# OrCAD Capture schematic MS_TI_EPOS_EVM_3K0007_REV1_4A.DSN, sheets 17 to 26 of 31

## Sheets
17 Pg17: UART #1 RS-232: size C
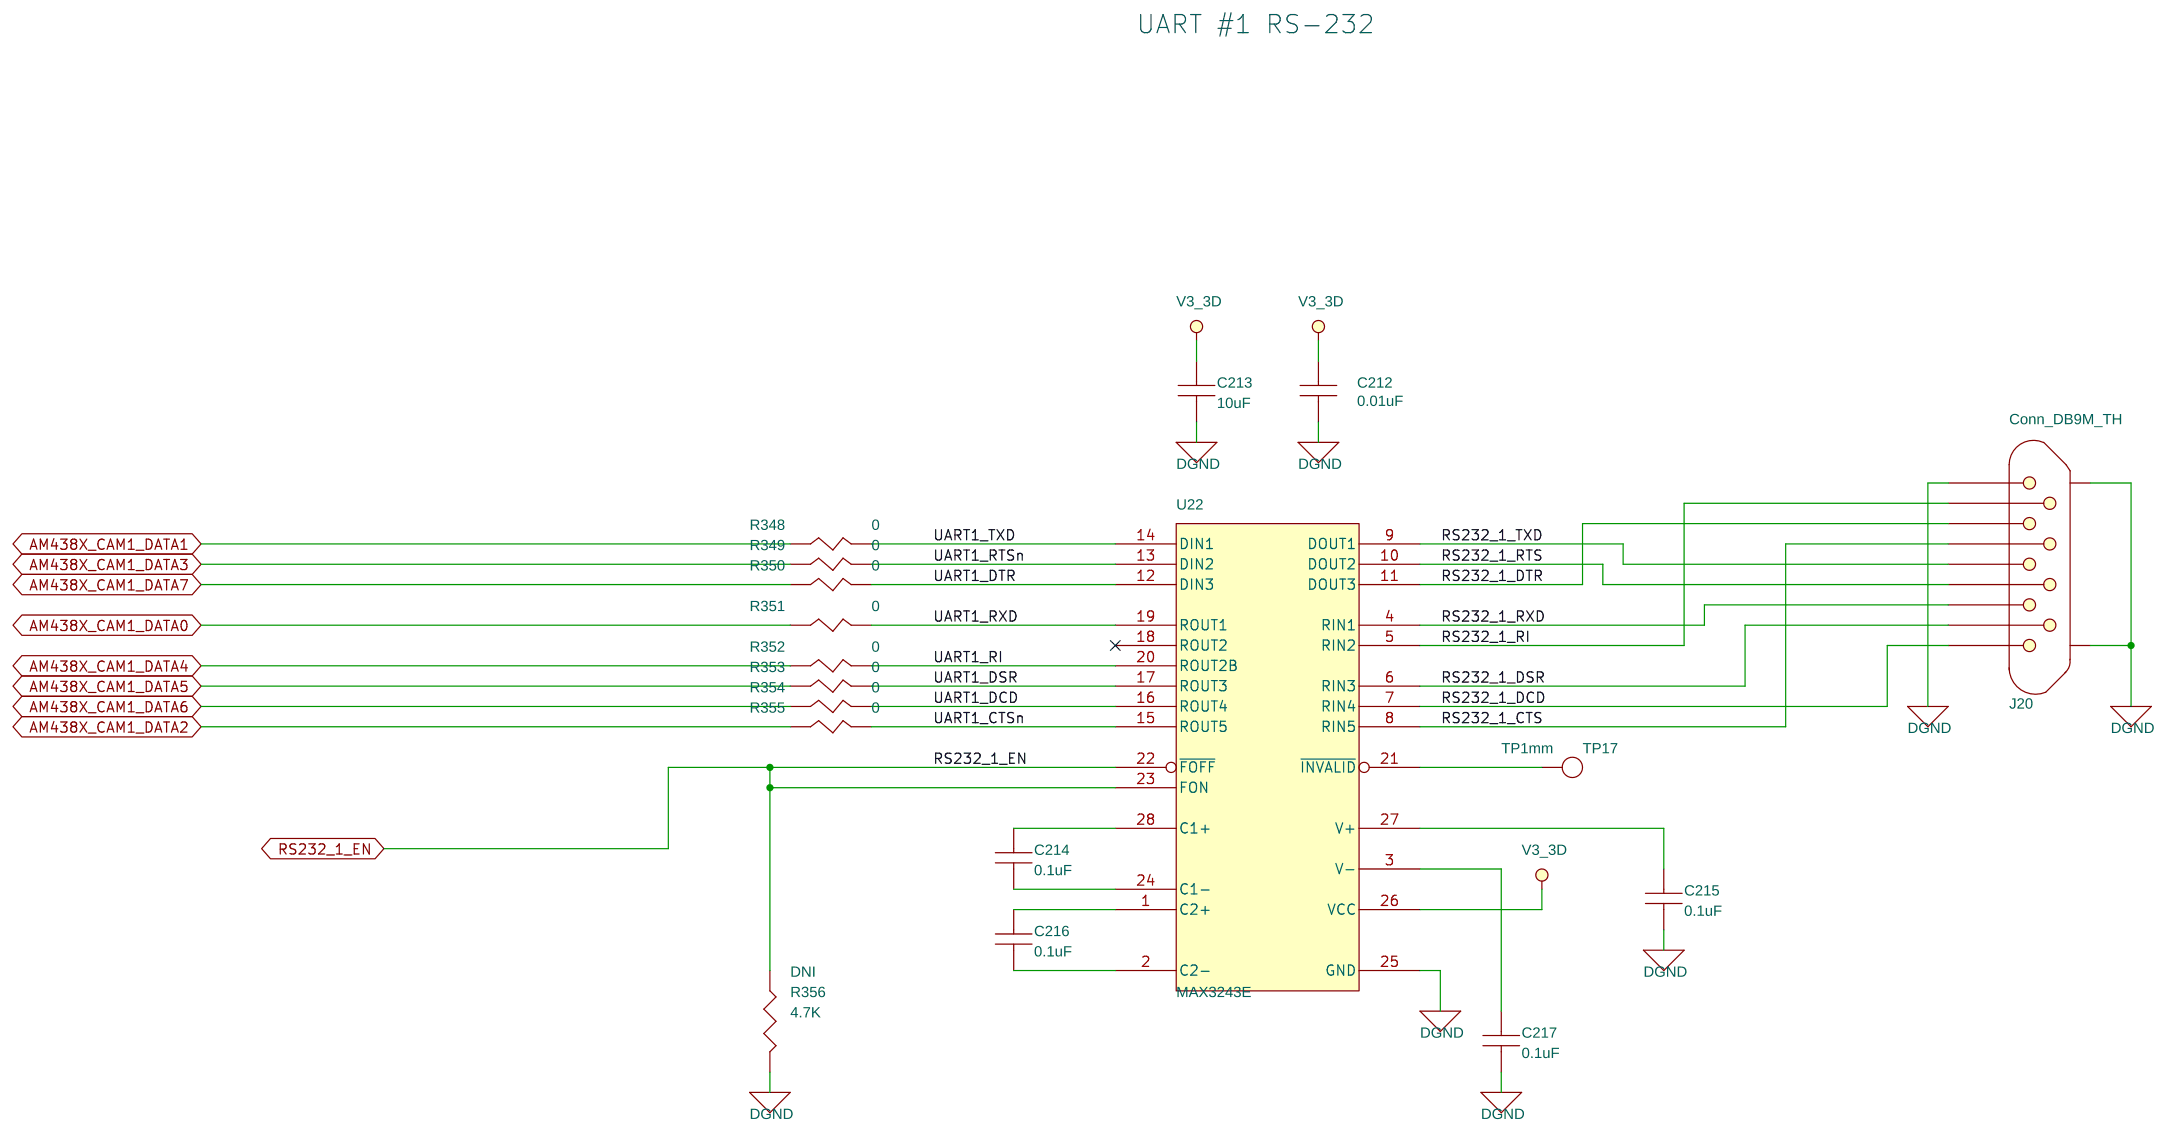
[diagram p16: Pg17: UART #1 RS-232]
18 Pg29: Power Monitor: size C
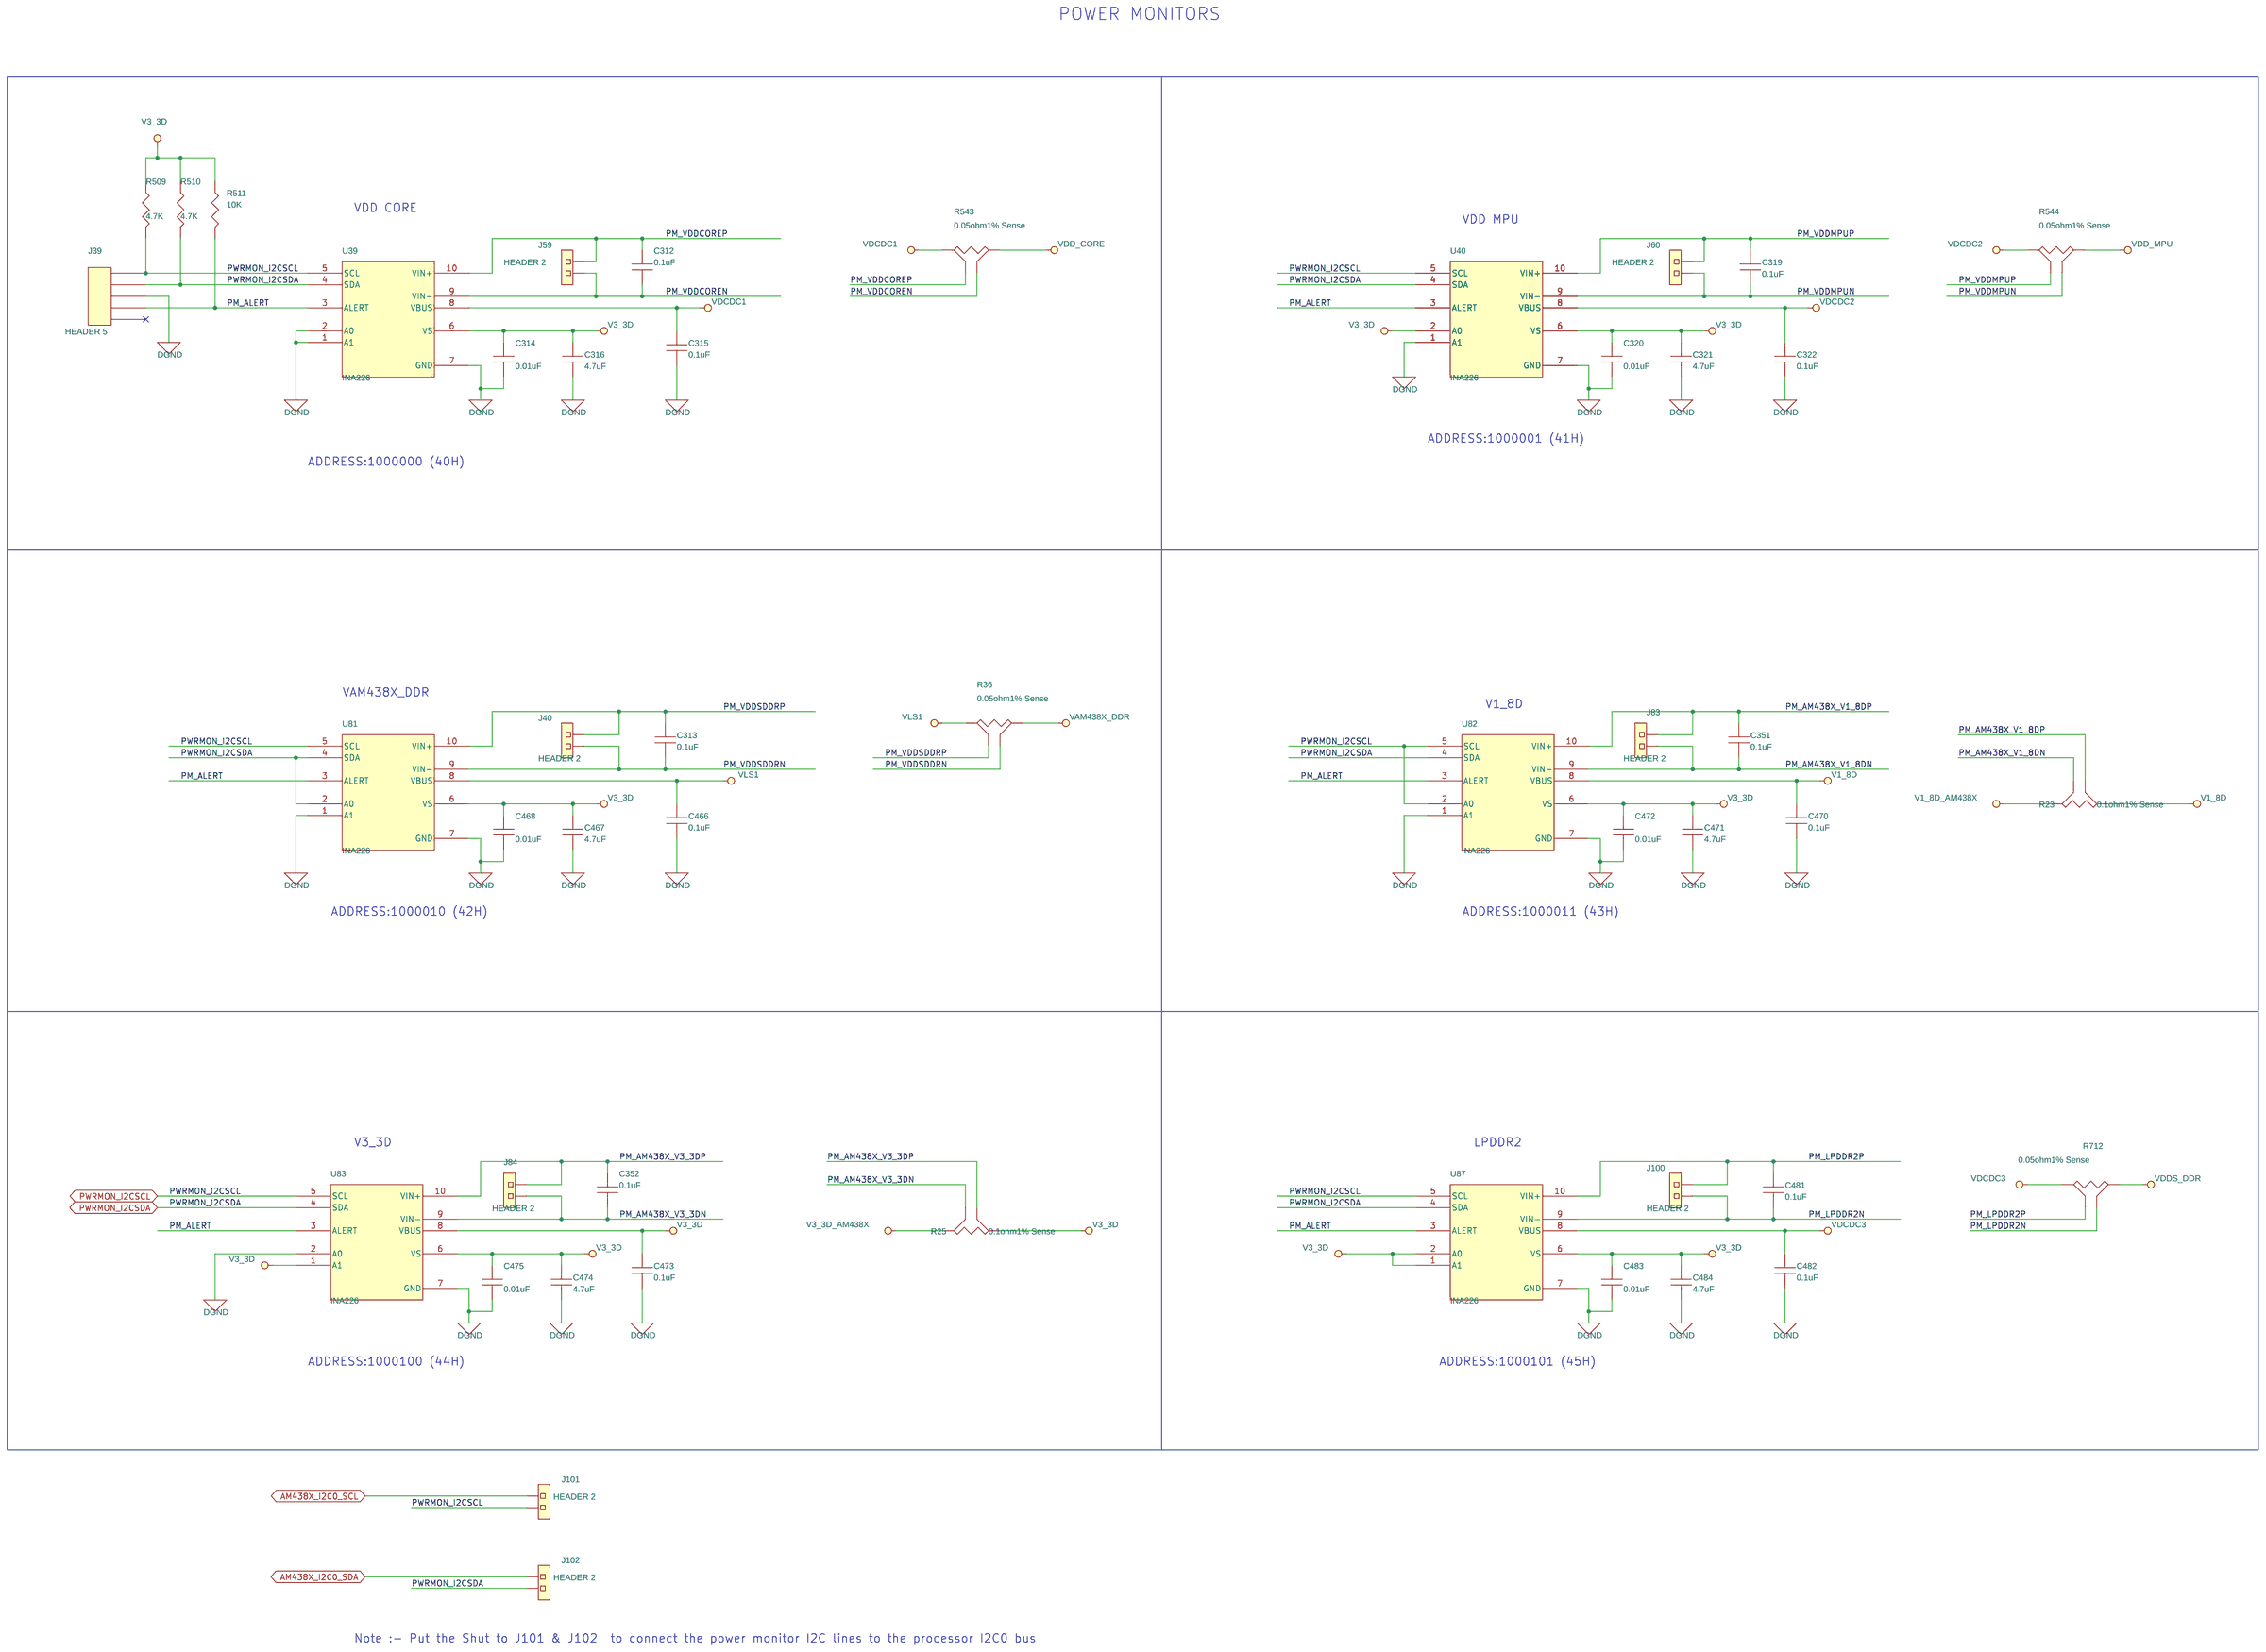
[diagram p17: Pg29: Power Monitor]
19 Pg18: Wireless COM8: size C
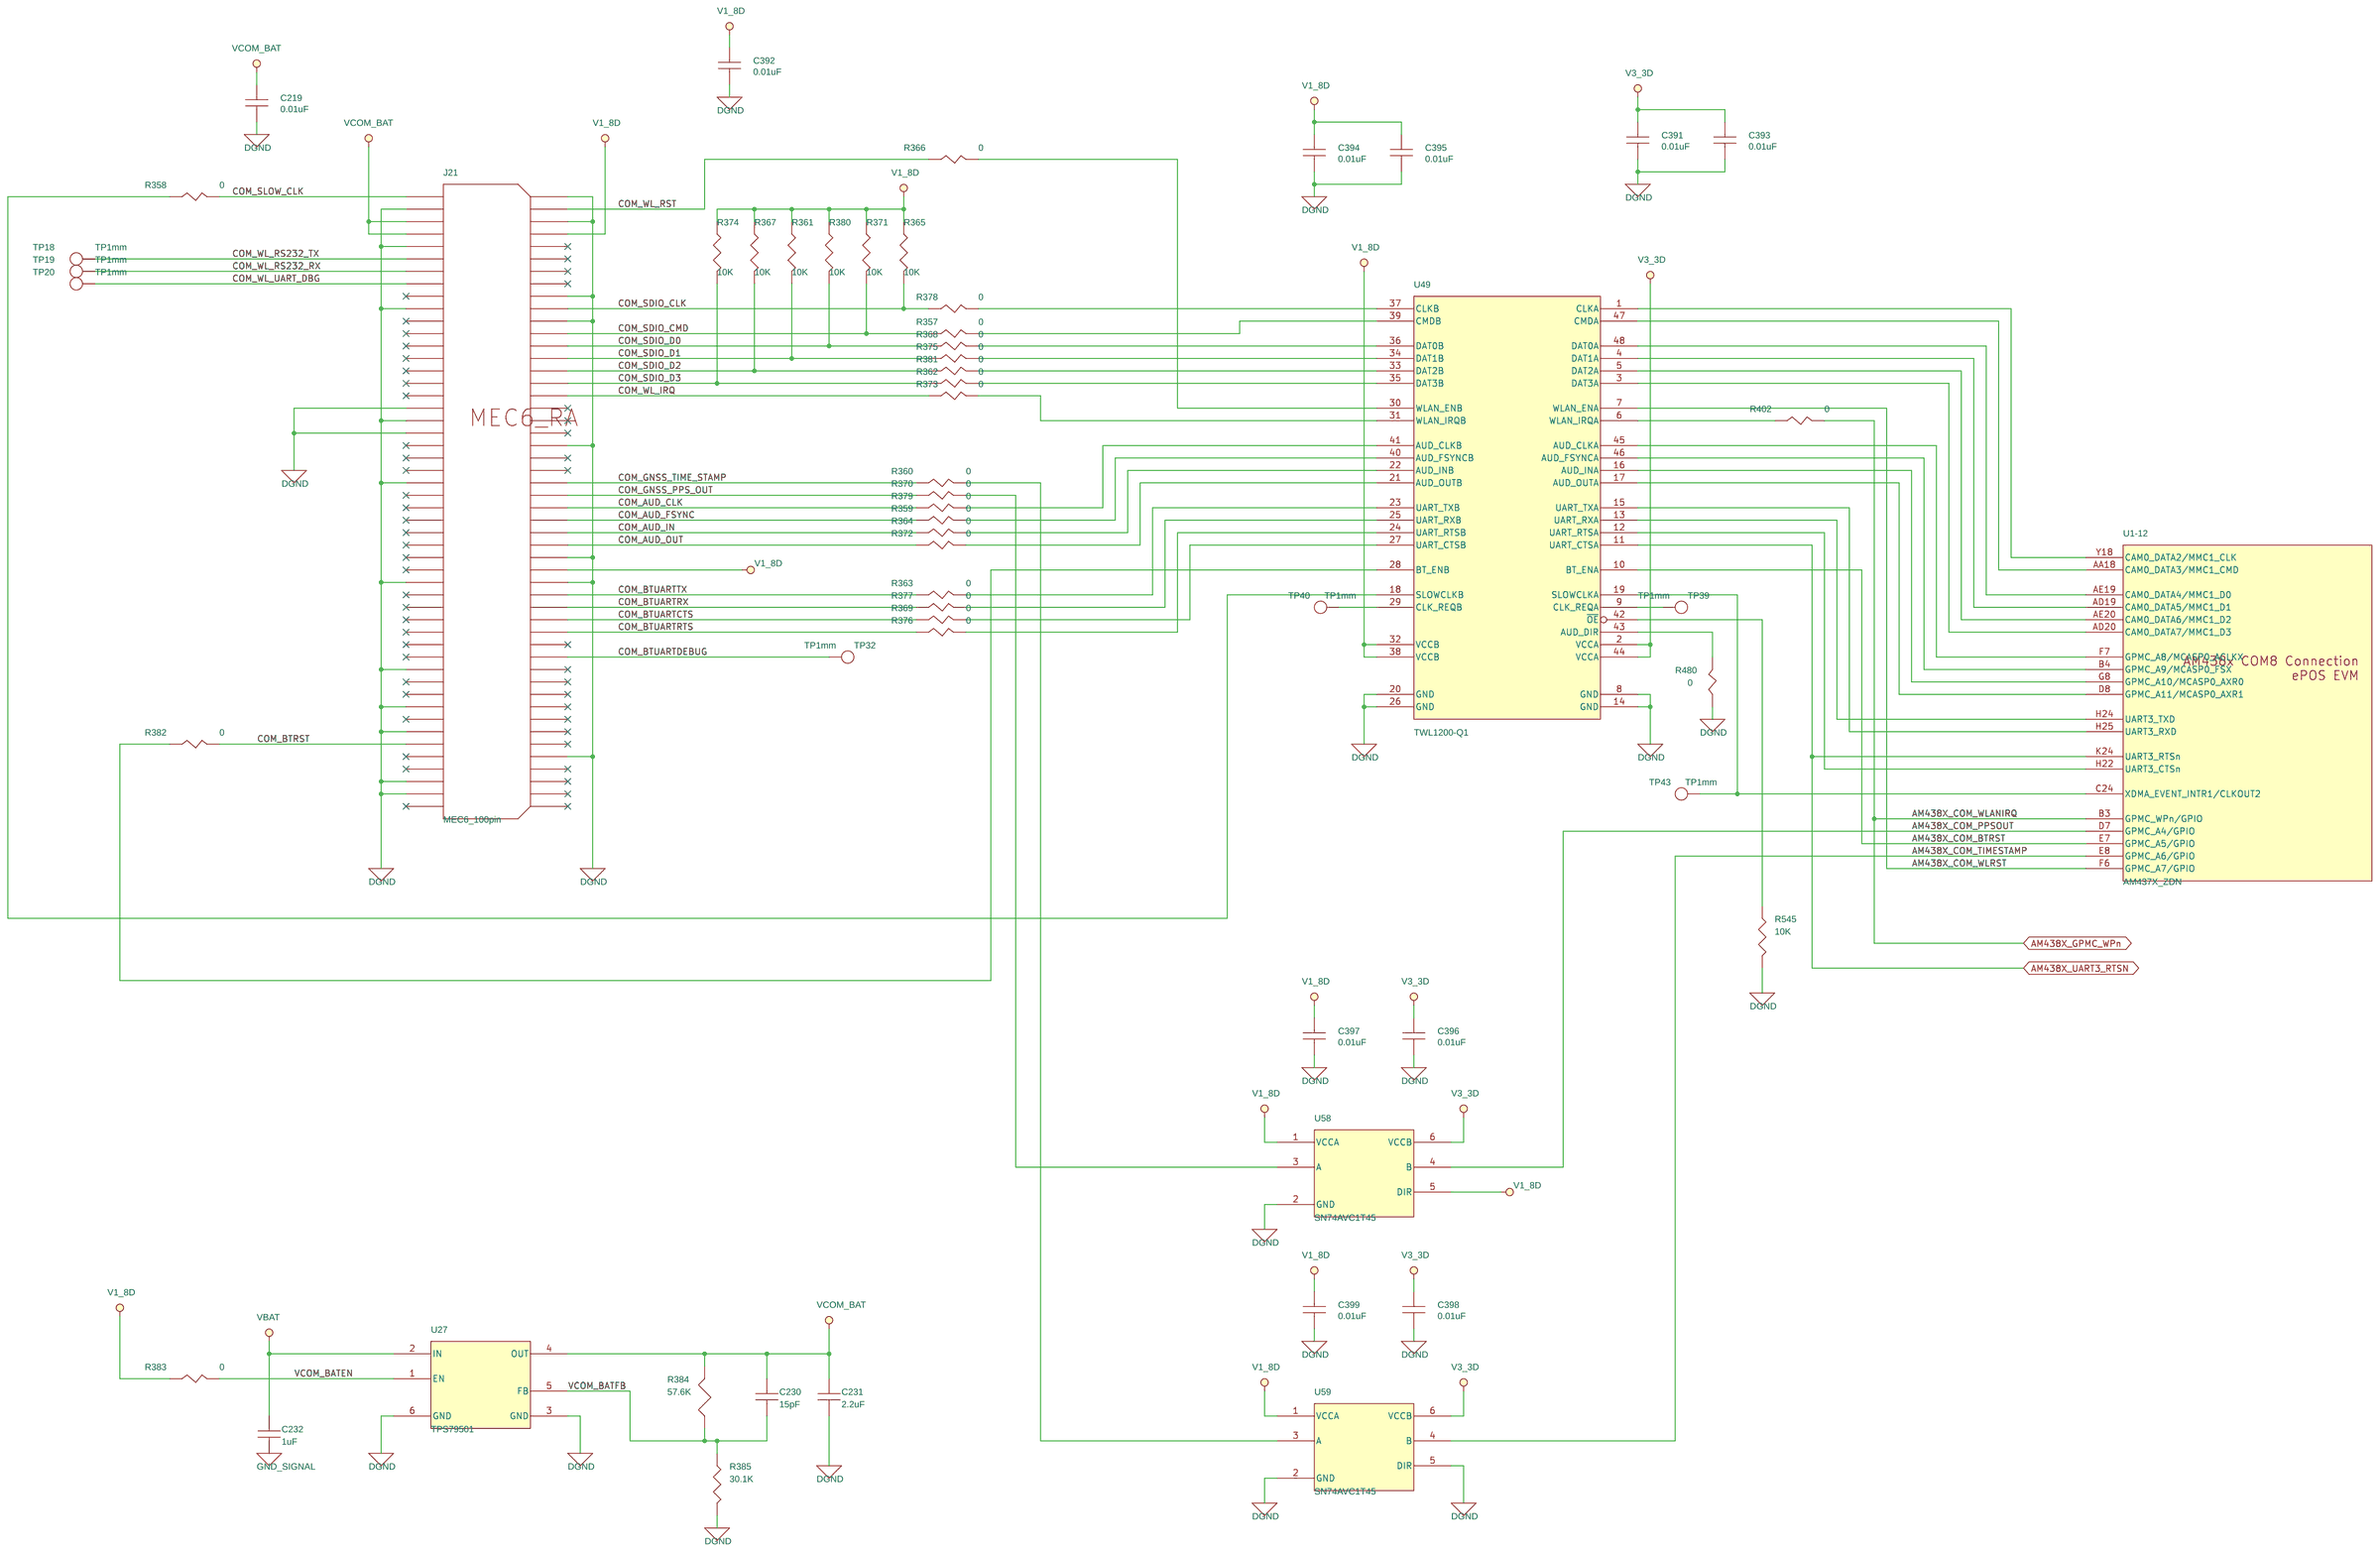
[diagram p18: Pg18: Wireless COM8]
20 Pg16: UART #0 RS-232: size C
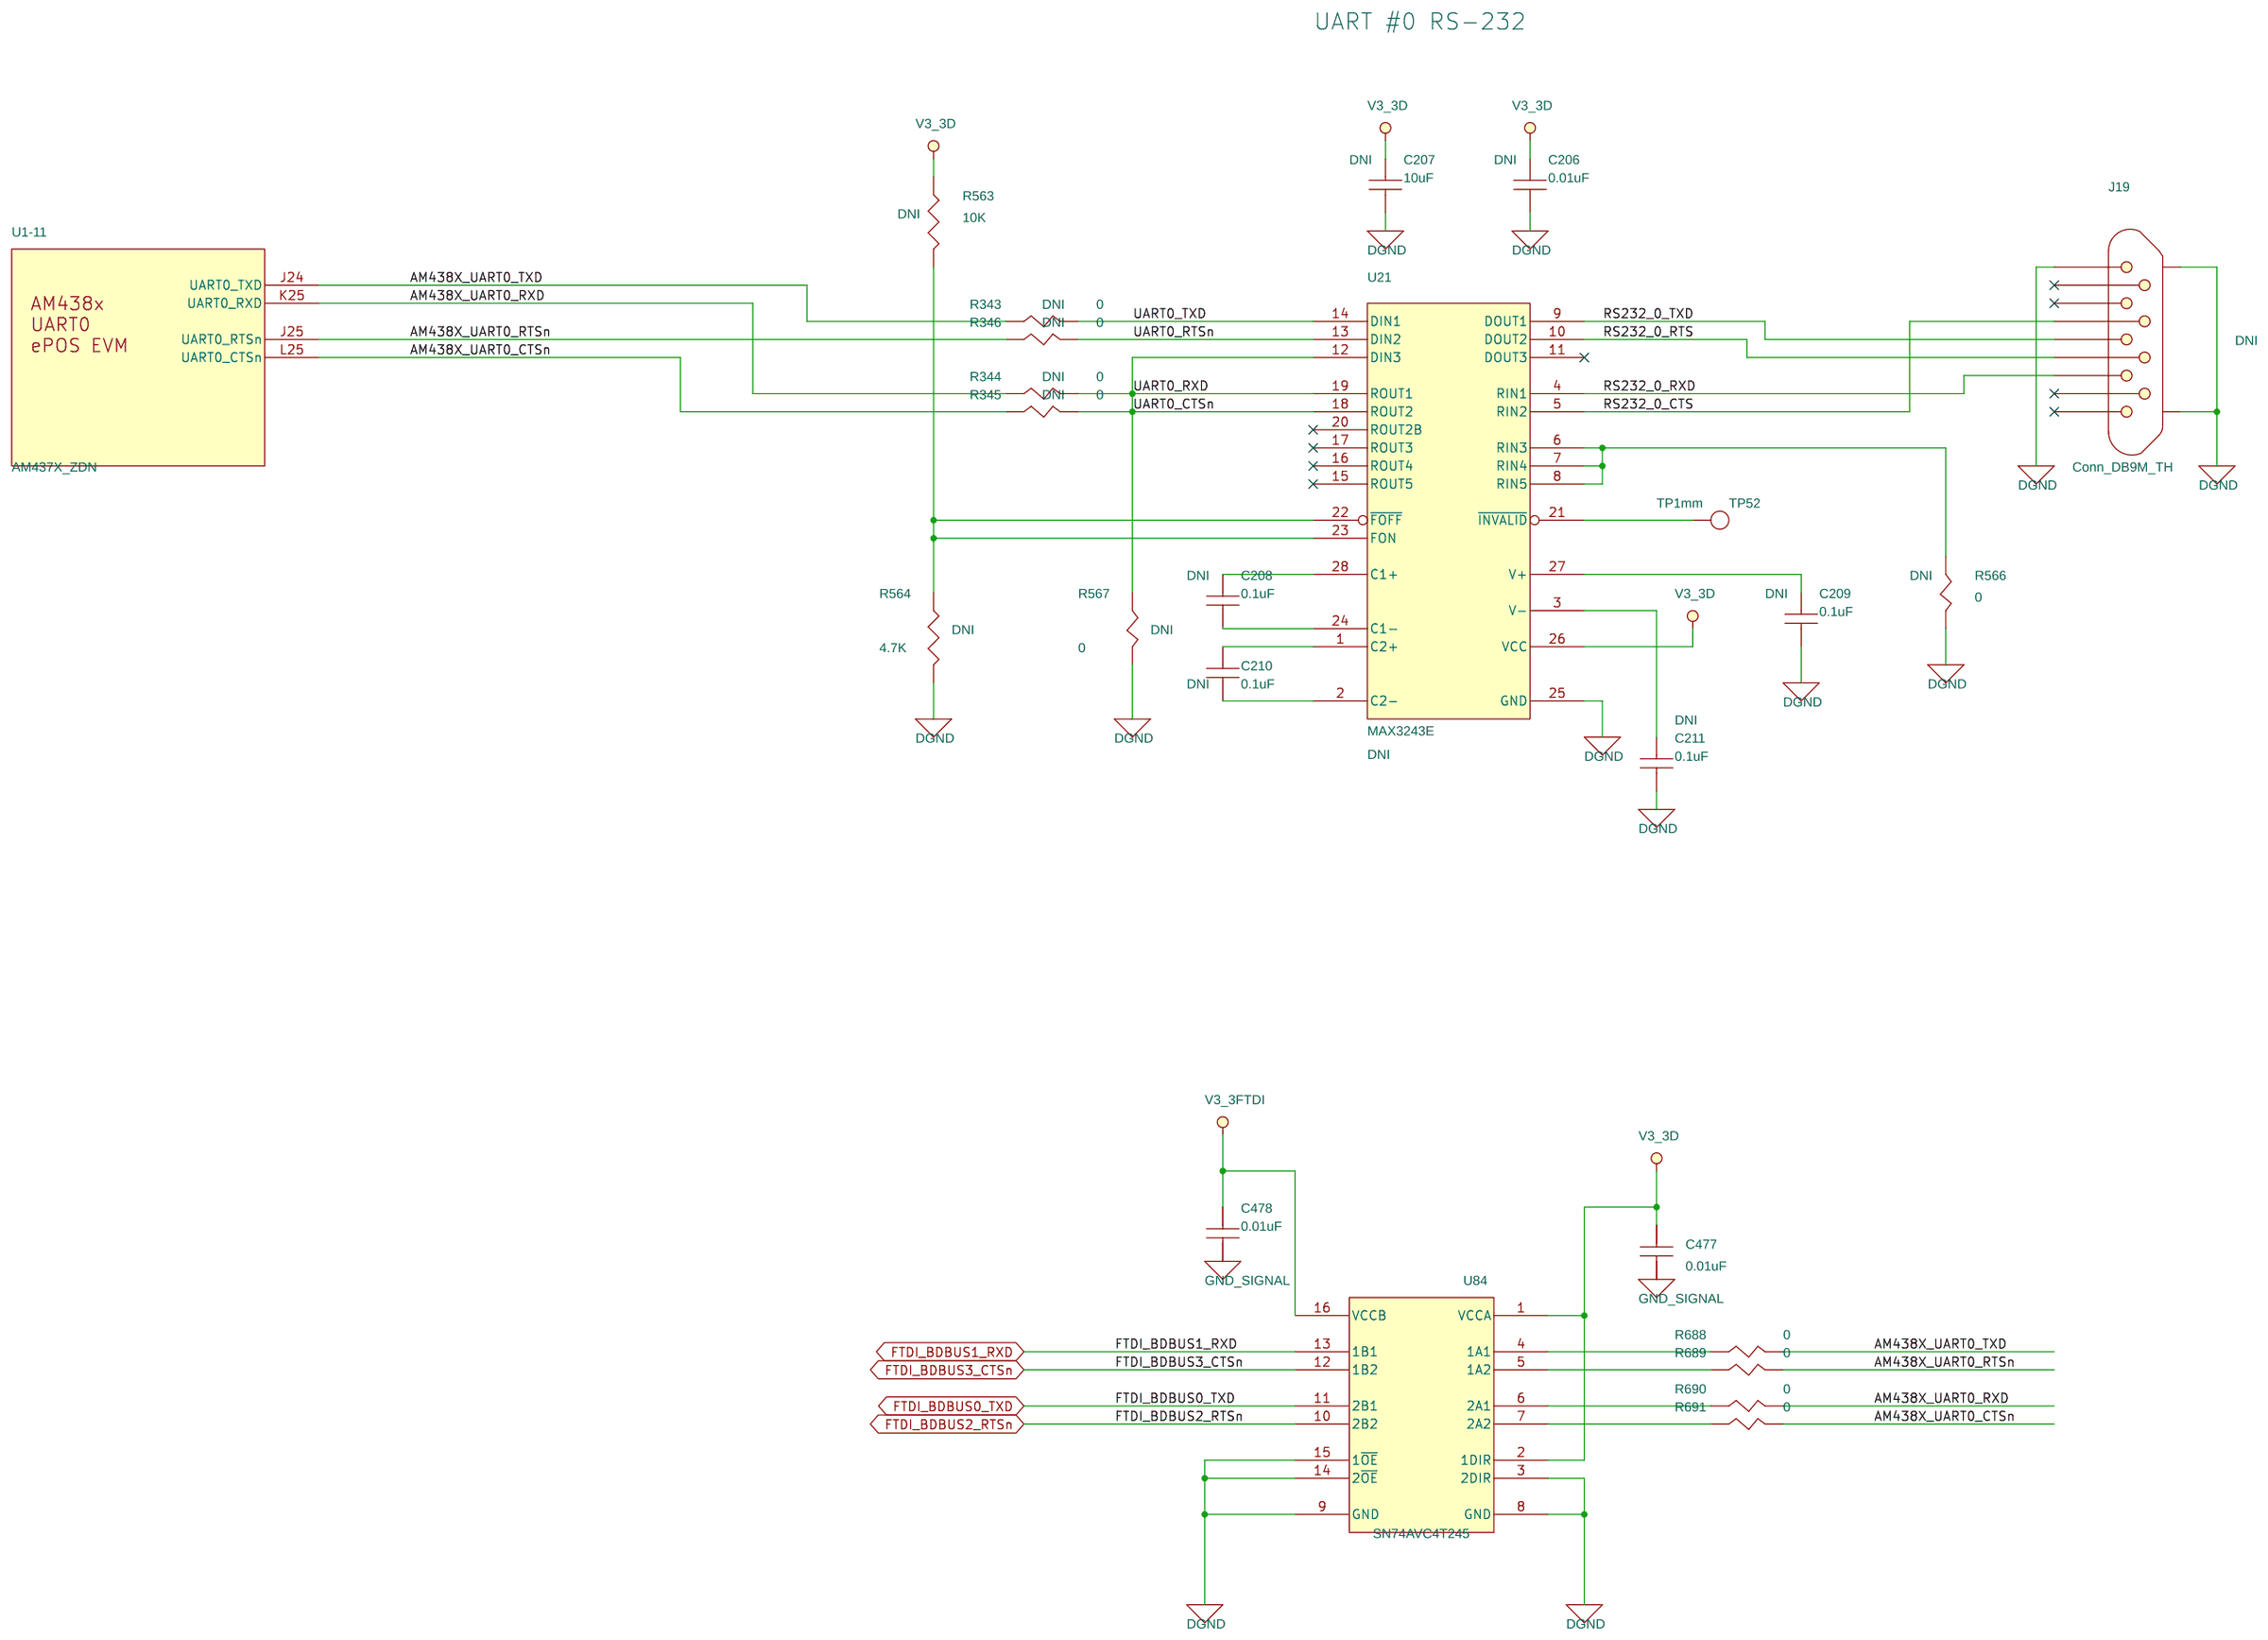
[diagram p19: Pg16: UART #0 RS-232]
21 Pg03: Processor Power: size C
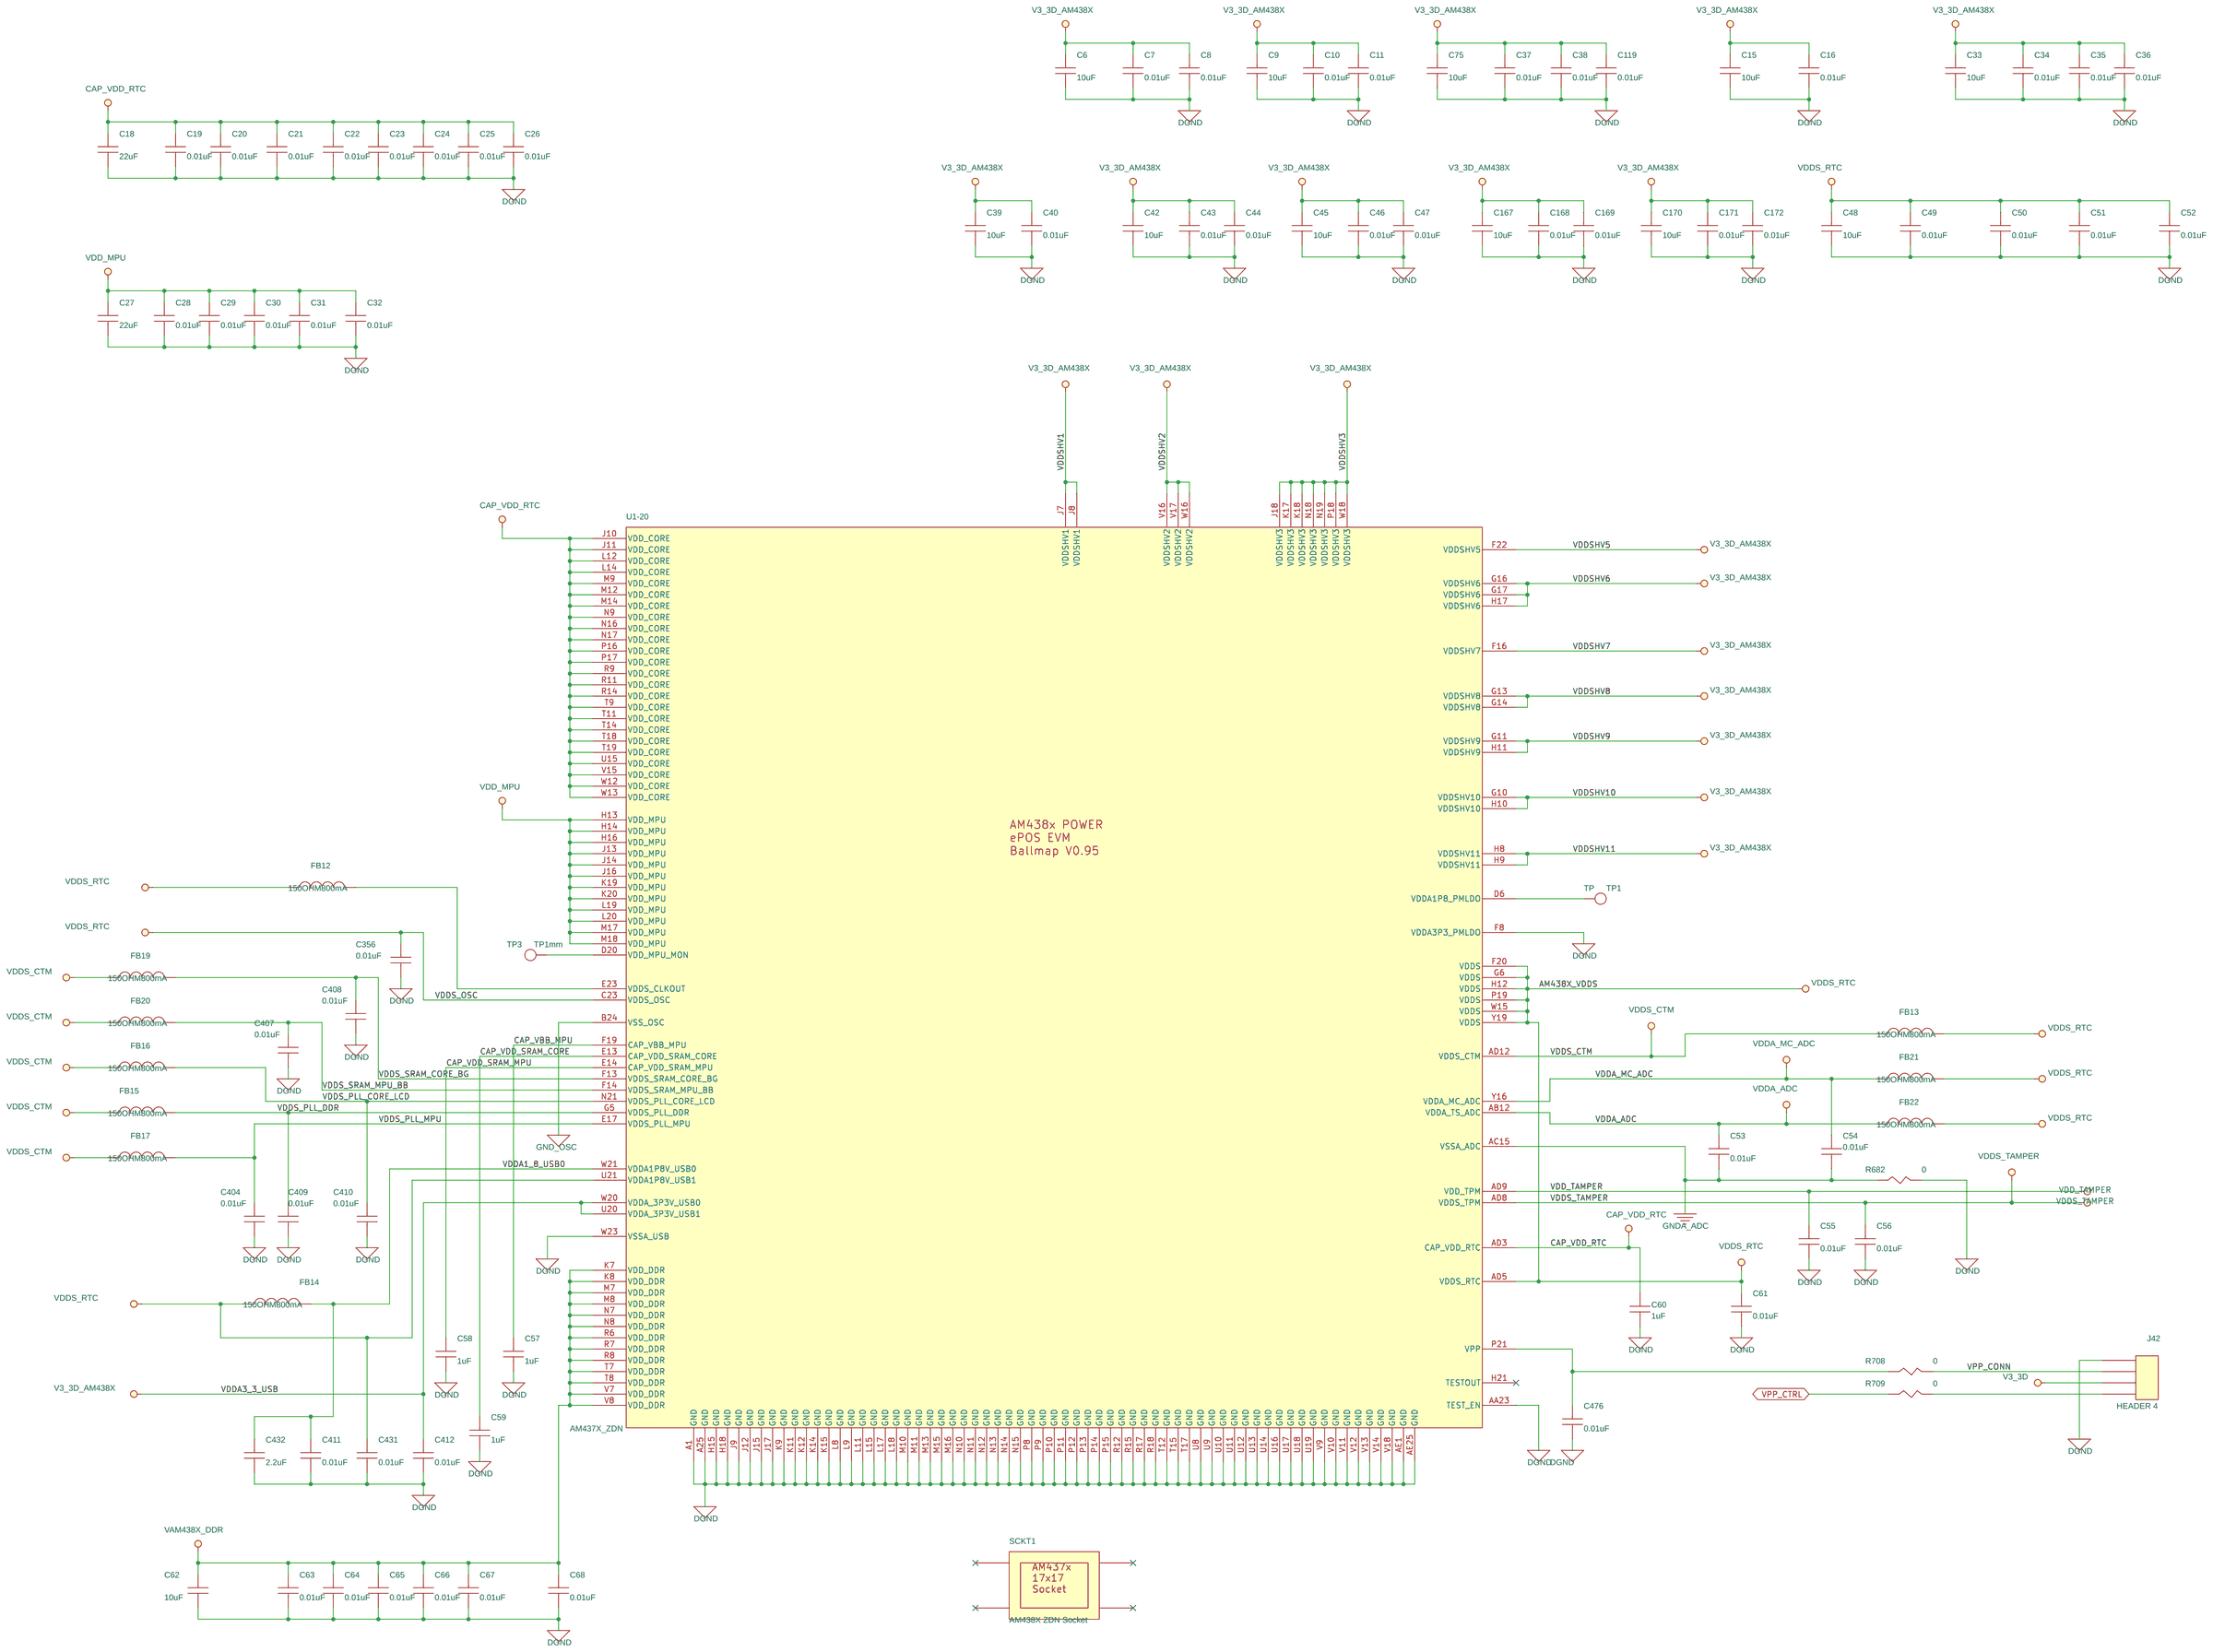
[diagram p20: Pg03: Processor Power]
22 Pg23: Tamper Signals: size C
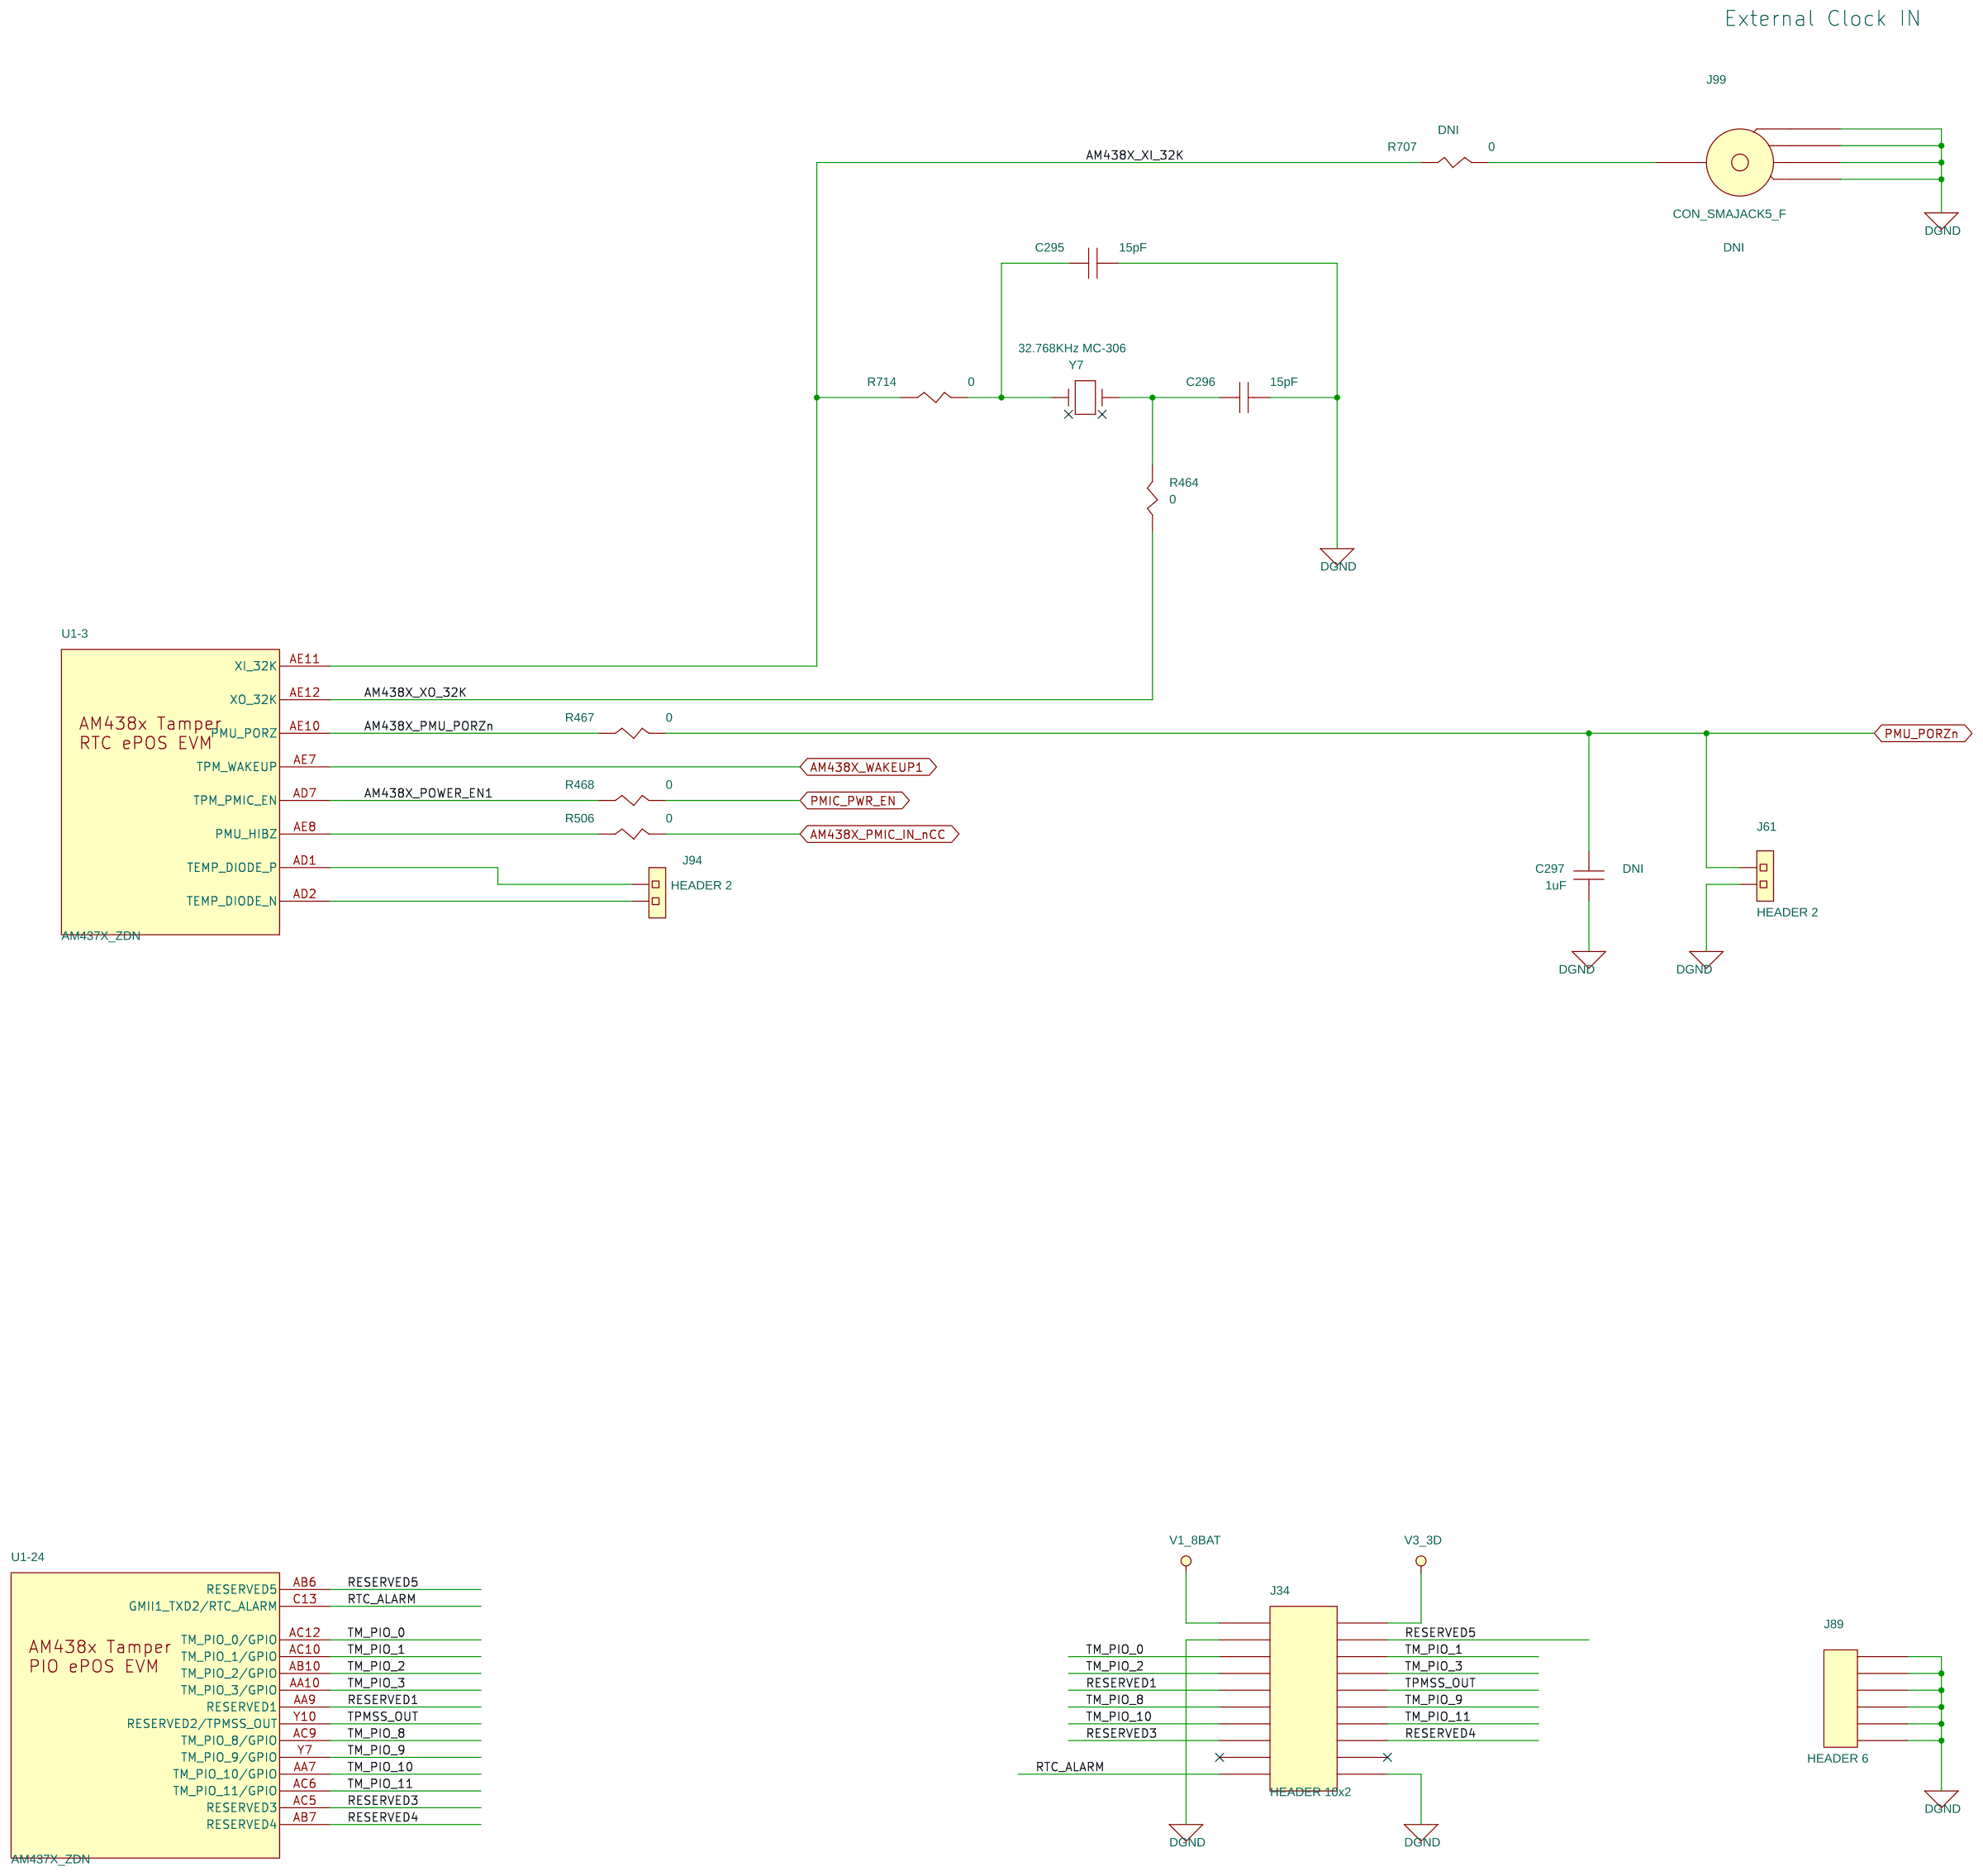
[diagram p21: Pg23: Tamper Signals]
23 Pg22: SPI Interfaces: size C
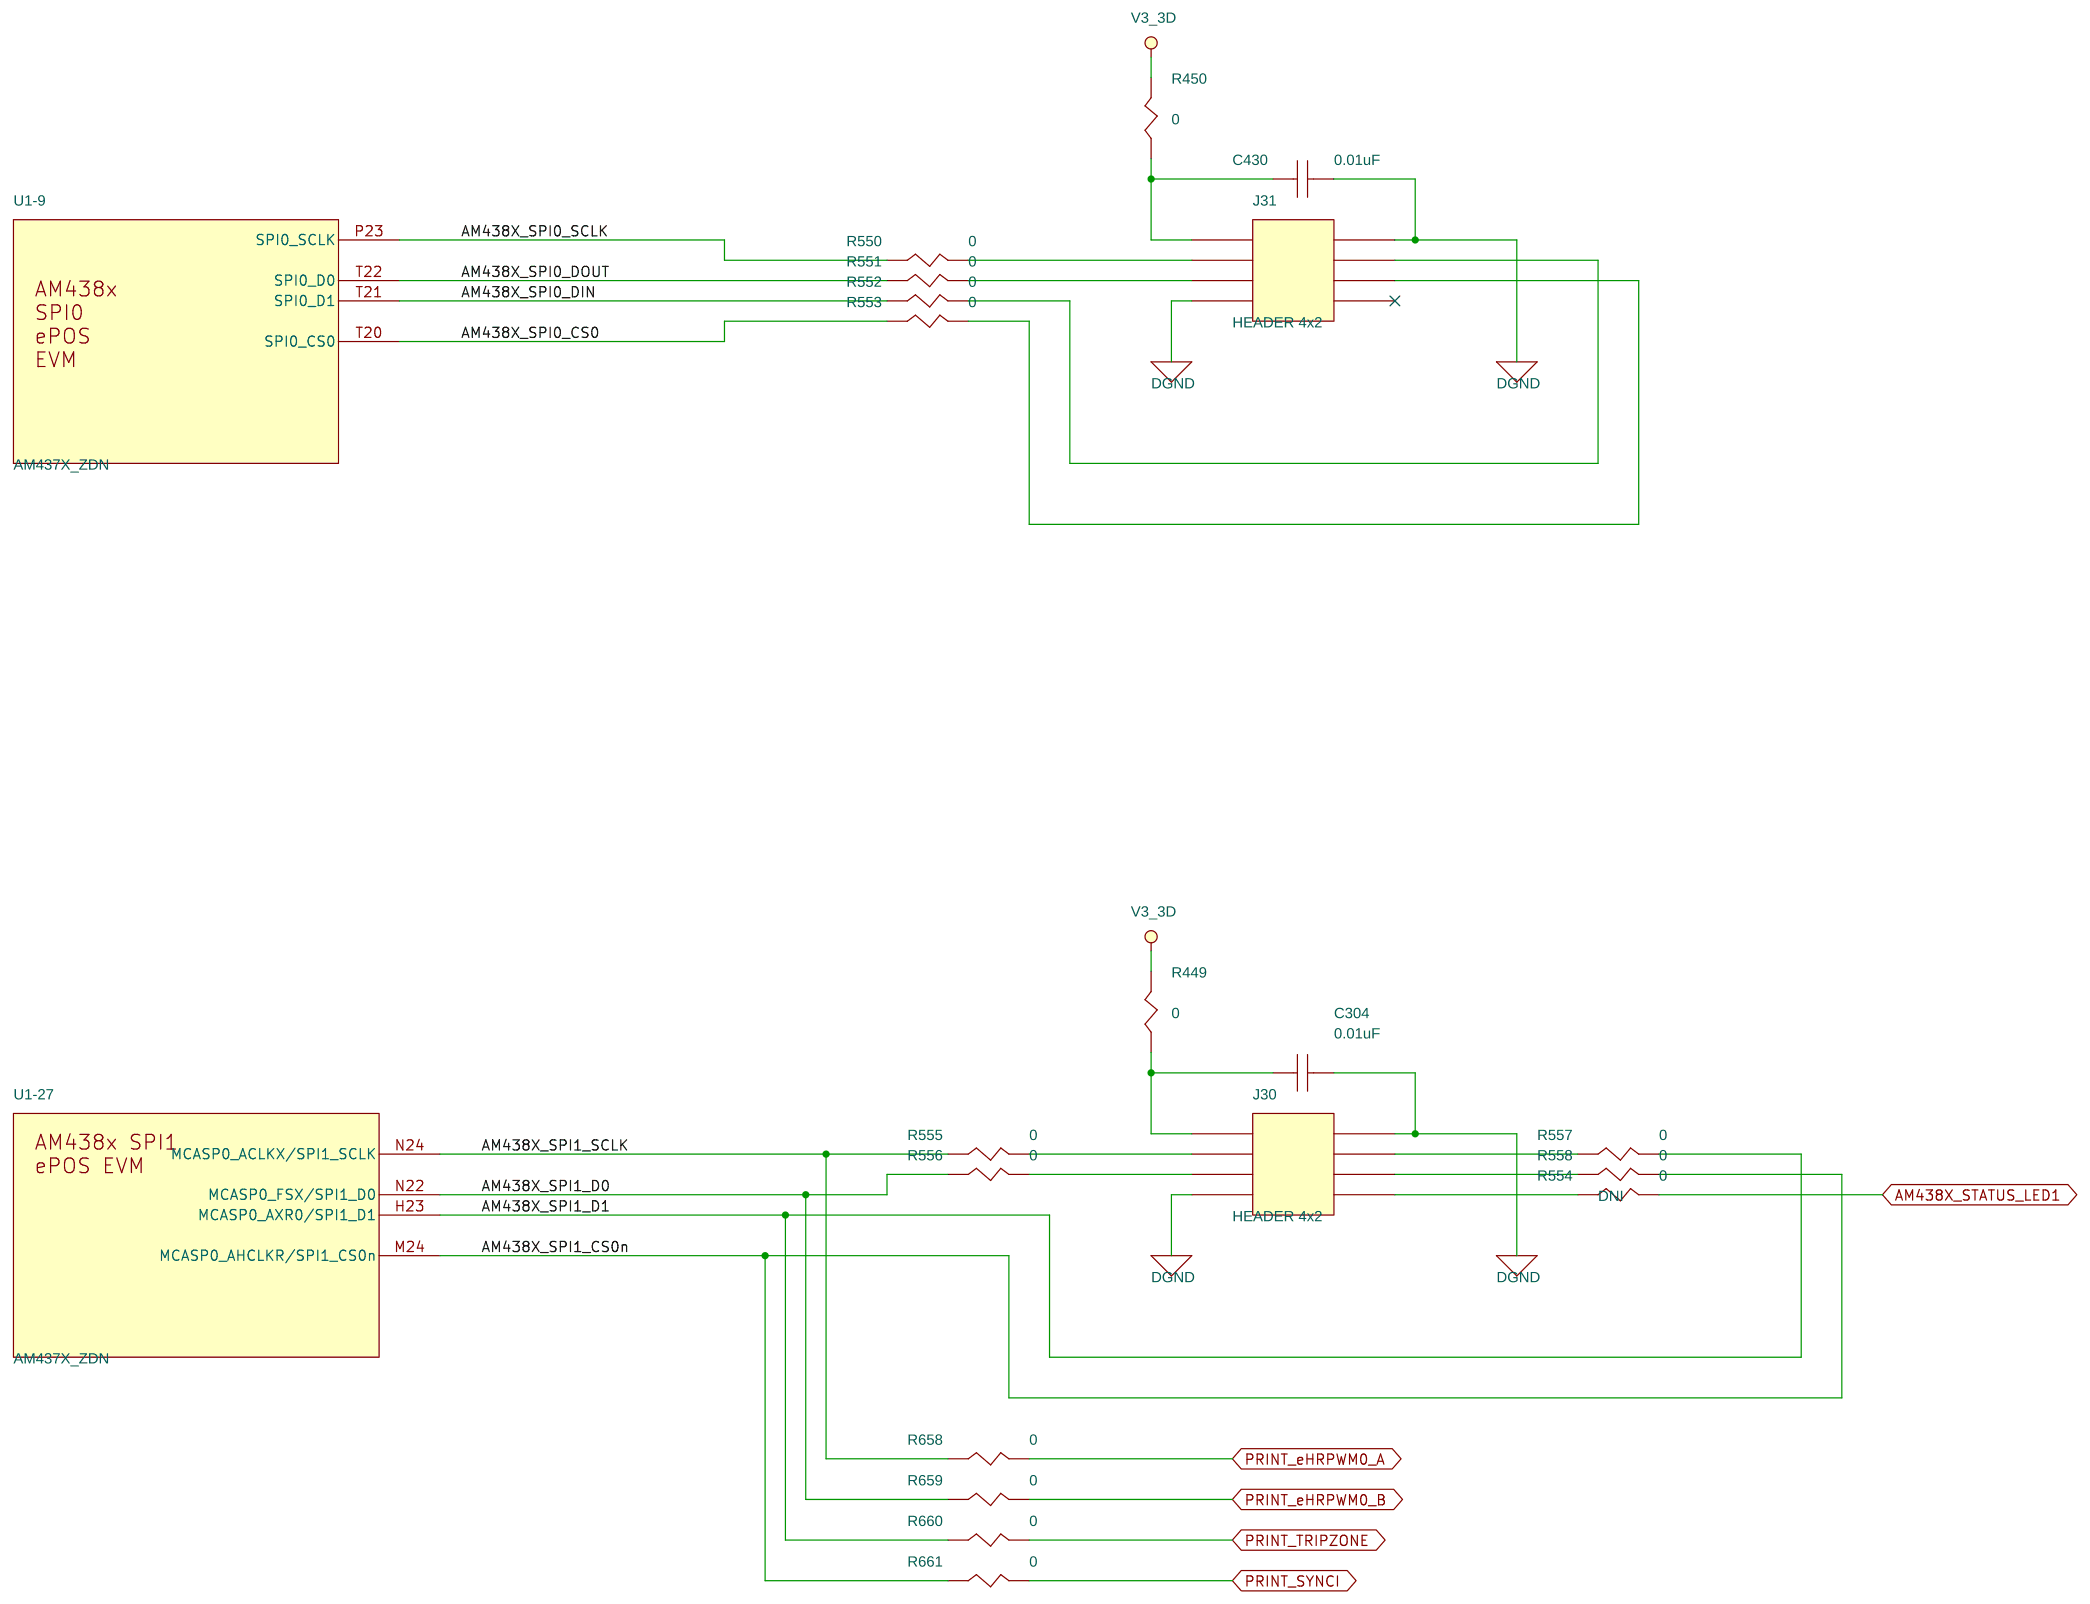
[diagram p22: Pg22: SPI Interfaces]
24 Pg30: GPIO Connector: size C
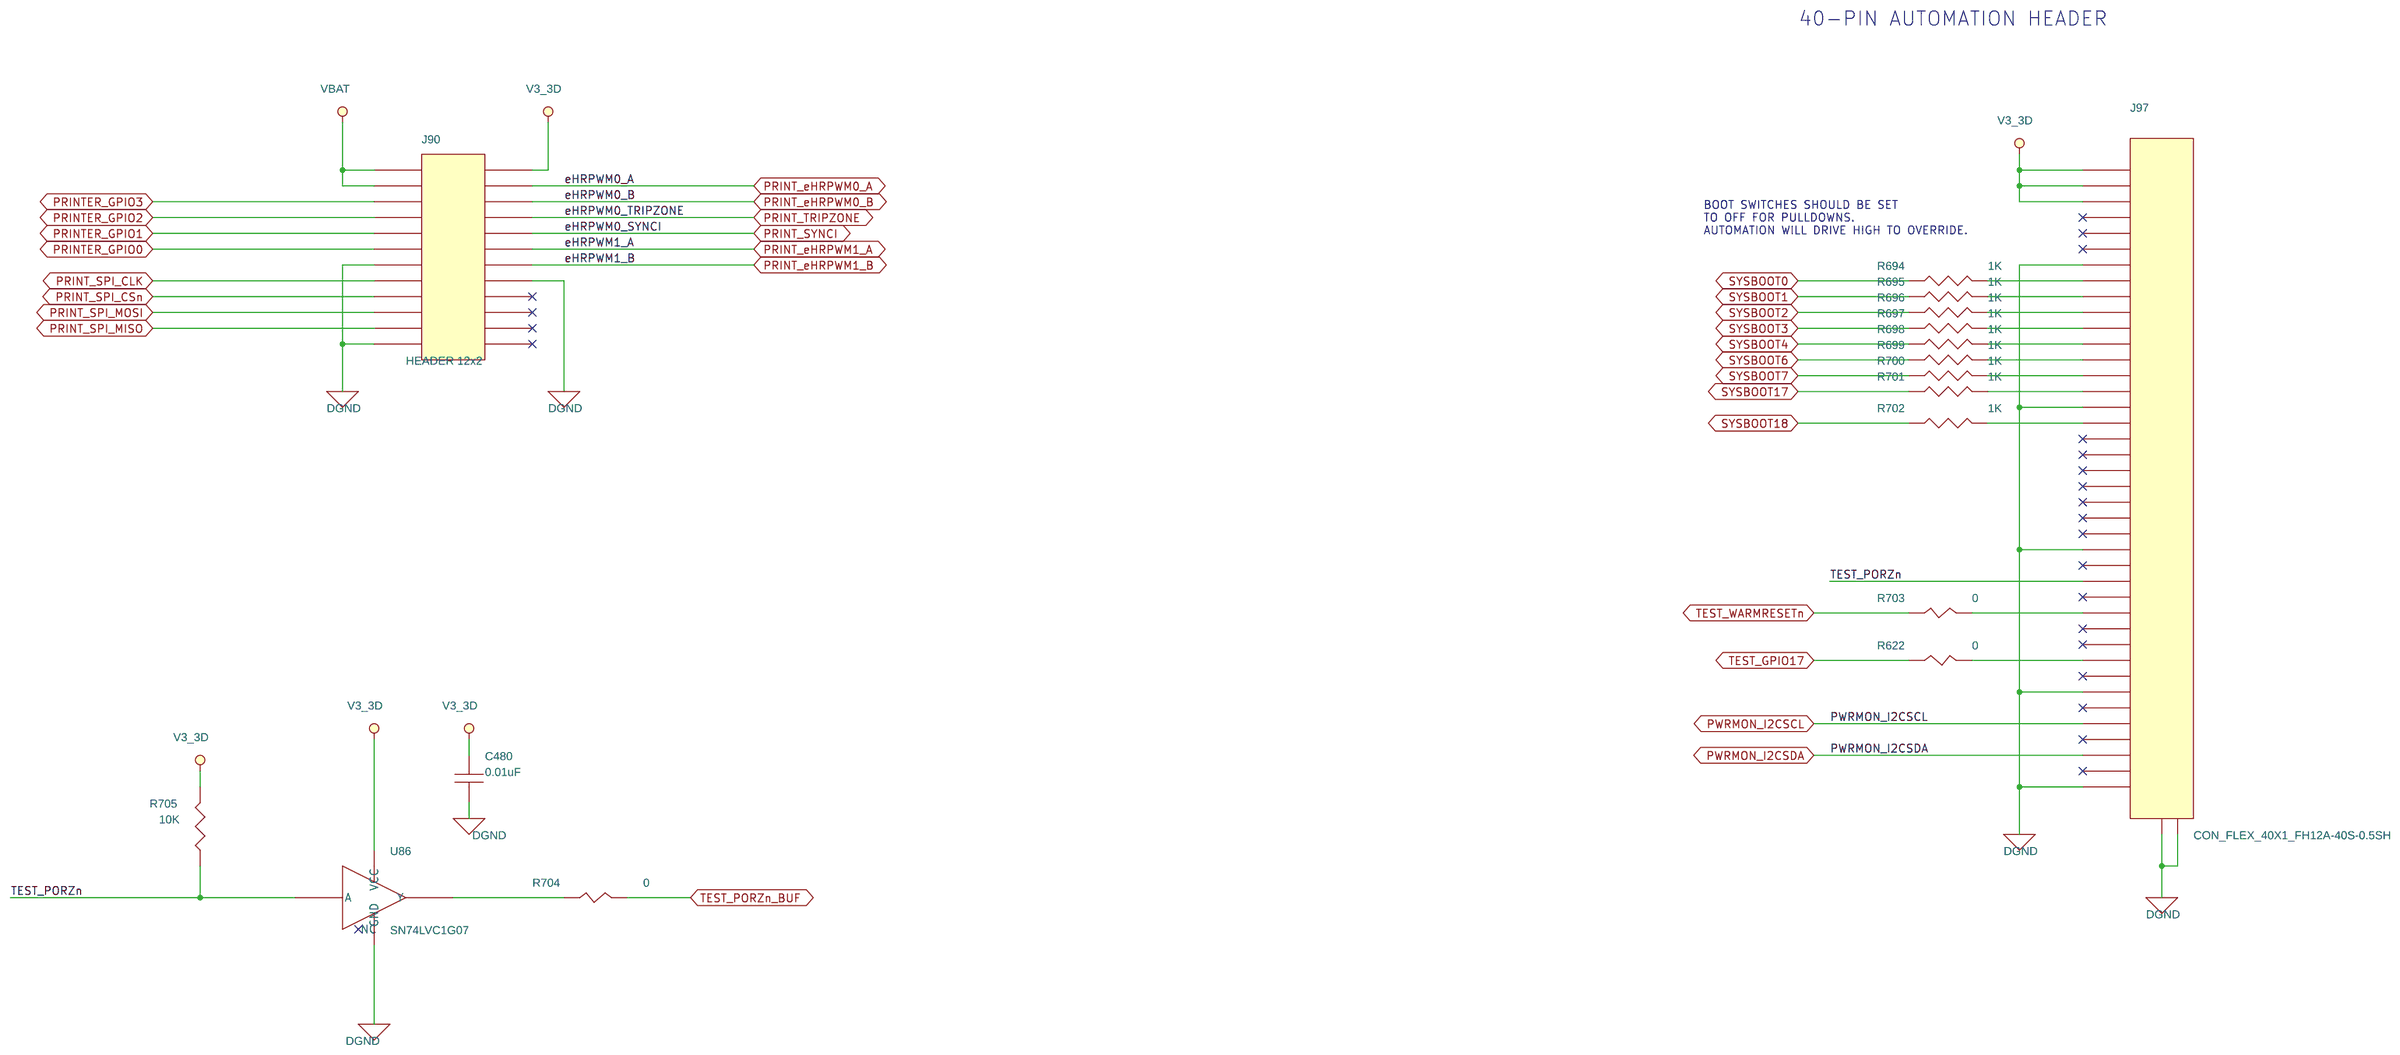
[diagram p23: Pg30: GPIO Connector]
25 Pg09: SDMMC0 Interface: size C
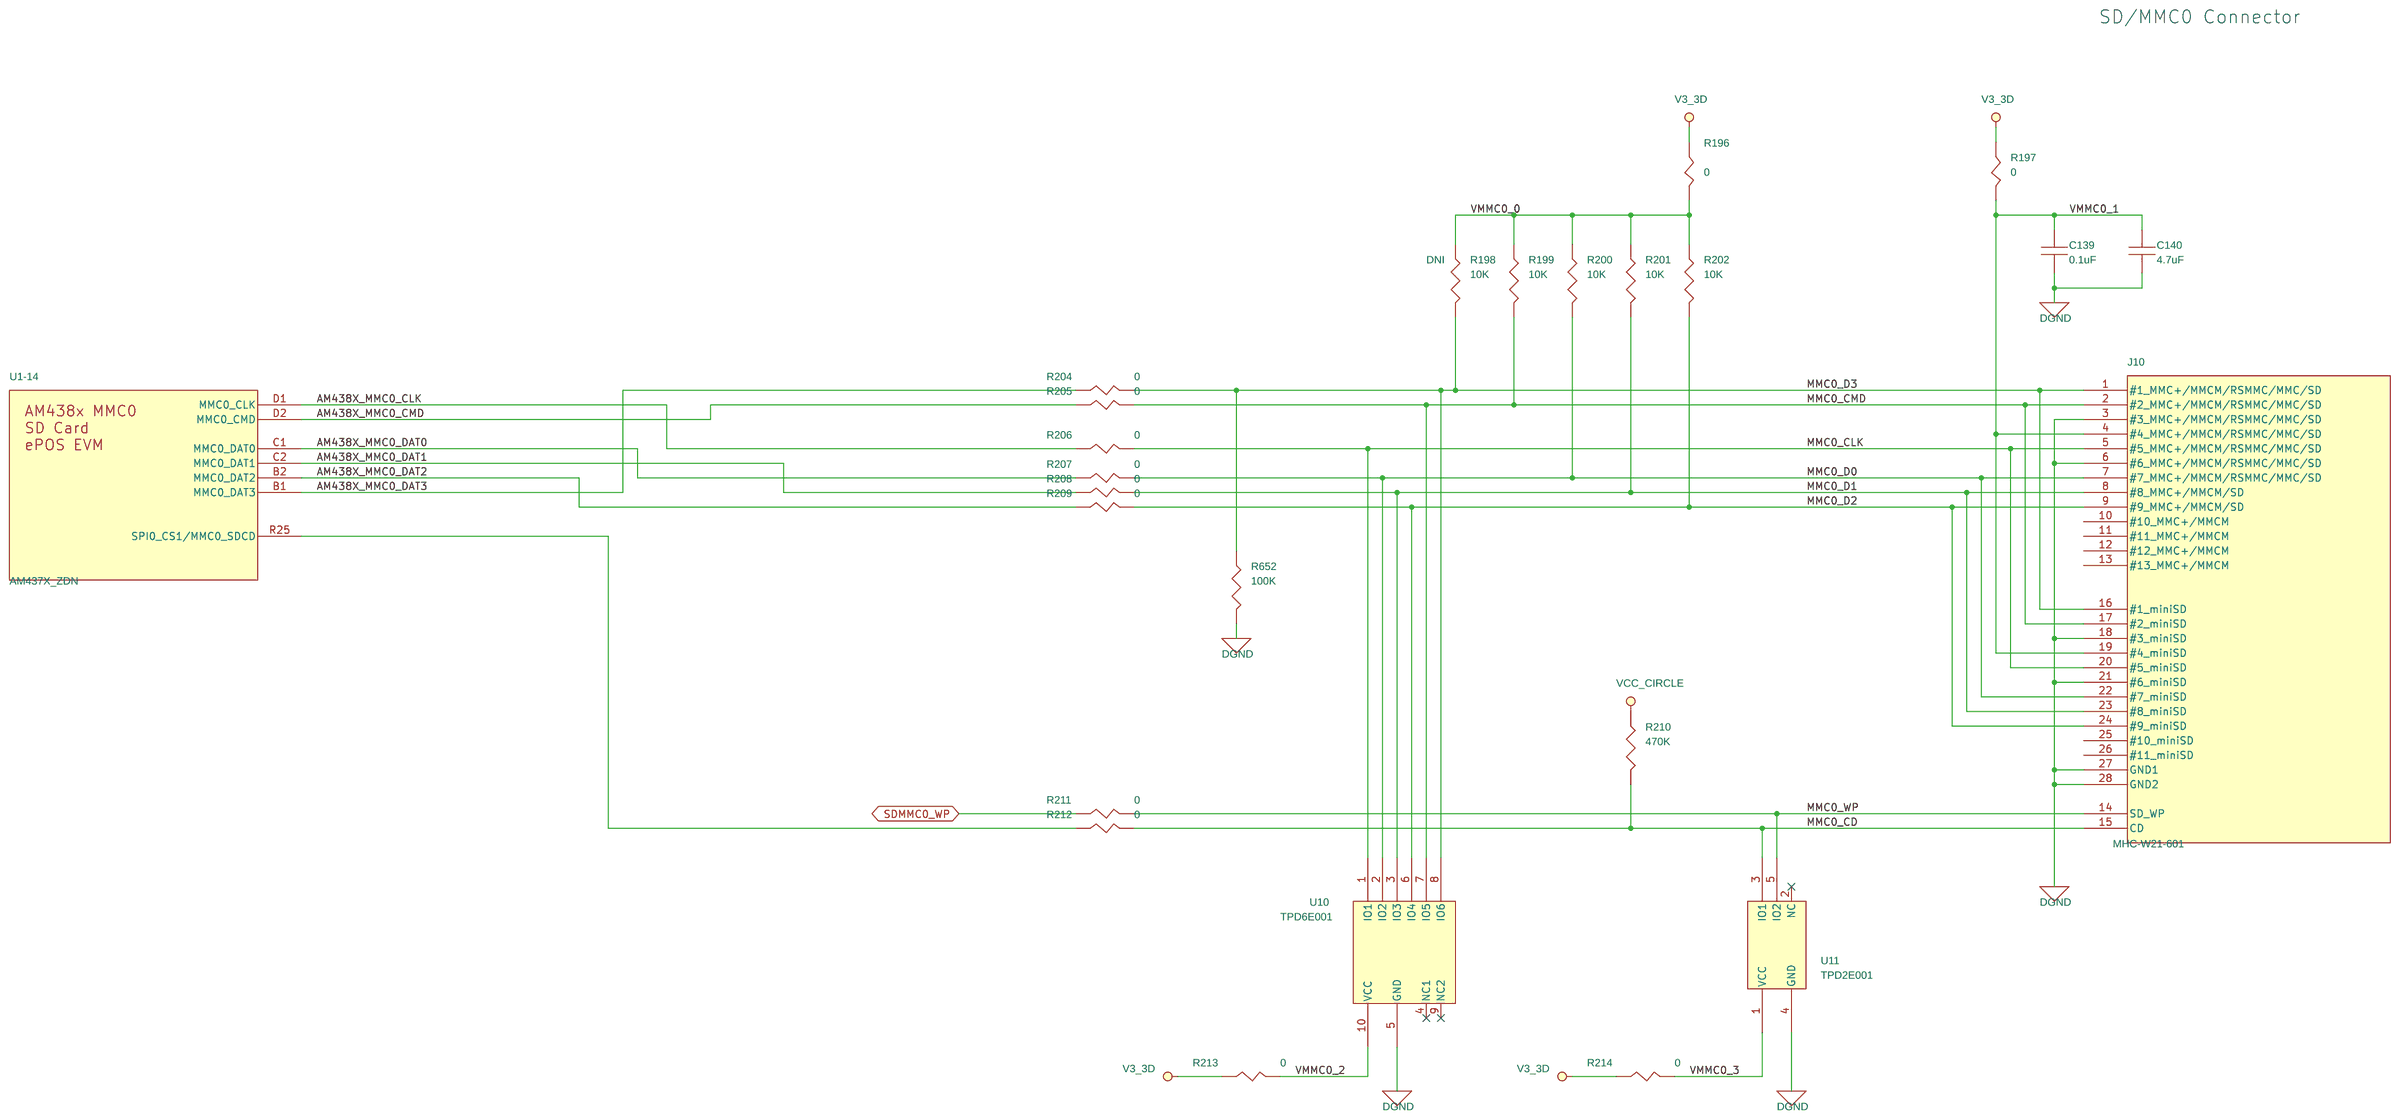
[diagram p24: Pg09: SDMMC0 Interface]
26 Pg07: Quad SPI Memory: size C
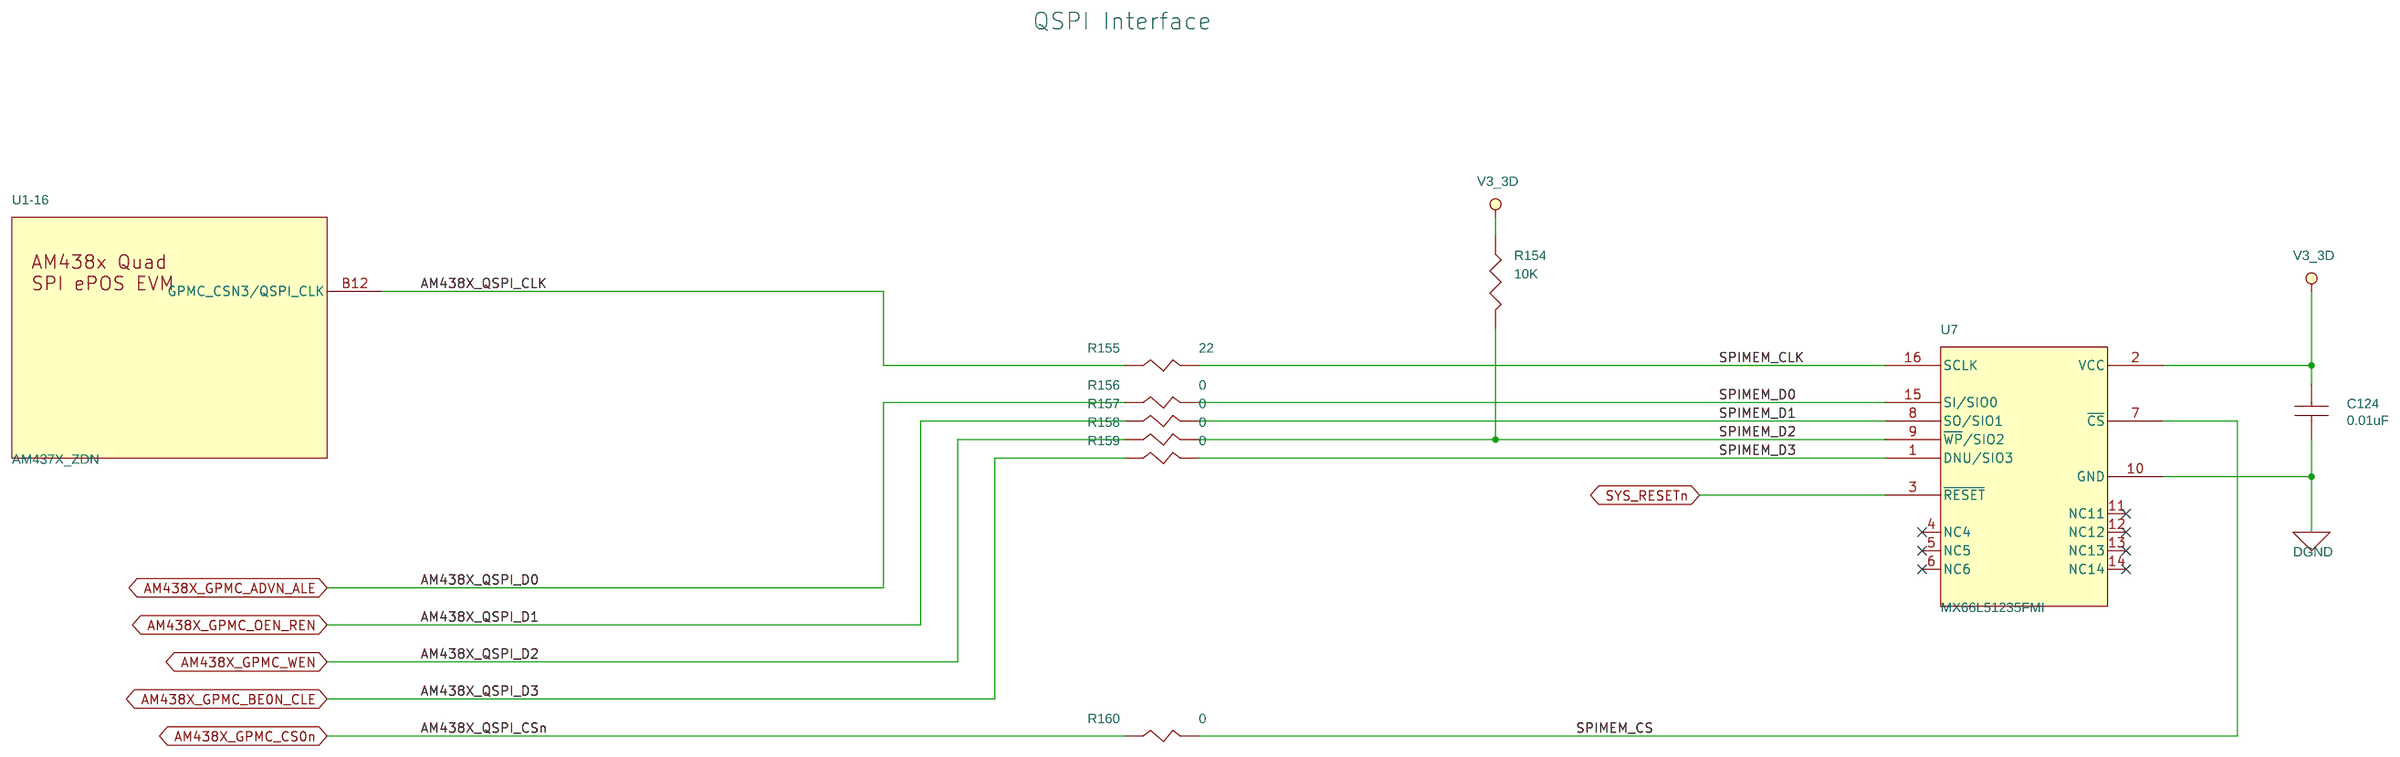
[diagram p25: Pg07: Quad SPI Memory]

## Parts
sheet Pg03: Processor Power
C6  10uF  [SM-7351-CAP-0805]
C7  0.01uF  [SM-7351-CAP-0402]
C8  0.01uF  [SM-7351-CAP-0402]
C9  10uF  [SM-7351-CAP-0805]
C10  0.01uF  [SM-7351-CAP-0402]
C11  0.01uF  [SM-7351-CAP-0402]
C15  10uF  [SM-7351-CAP-0805]
C16  0.01uF  [SM-7351-CAP-0402]
C18  22uF  [SM-7351-CAP-0805]
C19  0.01uF  [SM-7351-CAP-0402]
C20  0.01uF  [SM-7351-CAP-0402]
C21  0.01uF  [SM-7351-CAP-0402]
C22  0.01uF  [SM-7351-CAP-0402]
C23  0.01uF  [SM-7351-CAP-0402]
C24  0.01uF  [SM-7351-CAP-0402]
C25  0.01uF  [SM-7351-CAP-0402]
C26  0.01uF  [SM-7351-CAP-0402]
C27  22uF  [SM-7351-CAP-0805]
C28  0.01uF  [SM-7351-CAP-0402]
C29  0.01uF  [SM-7351-CAP-0402]
C30  0.01uF  [SM-7351-CAP-0402]
C31  0.01uF  [SM-7351-CAP-0402]
C32  0.01uF  [SM-7351-CAP-0402]
C33  10uF  [SM-7351-CAP-0805]
C34  0.01uF  [SM-7351-CAP-0402]
C35  0.01uF  [SM-7351-CAP-0402]
C36  0.01uF  [SM-7351-CAP-0402]
C37  0.01uF  [SM-7351-CAP-0402]
C38  0.01uF  [SM-7351-CAP-0402]
C39  10uF  [SM-7351-CAP-0805]
C40  0.01uF  [SM-7351-CAP-0402]
C42  10uF  [SM-7351-CAP-0805]
C43  0.01uF  [SM-7351-CAP-0402]
C44  0.01uF  [SM-7351-CAP-0402]
C45  10uF  [SM-7351-CAP-0805]
C46  0.01uF  [SM-7351-CAP-0402]
C47  0.01uF  [SM-7351-CAP-0402]
C48  10uF  [SM-7351-CAP-0805]
C49  0.01uF  [SM-7351-CAP-0402]
C50  0.01uF  [SM-7351-CAP-0402]
C51  0.01uF  [SM-7351-CAP-0402]
C52  0.01uF  [SM-7351-CAP-0402]
C53  0.01uF  [SM-7351-CAP-0402]
C54  0.01uF  [SM-7351-CAP-0402]
C55  0.01uF  [SM-7351-CAP-0402]
C56  0.01uF  [SM-7351-CAP-0402]
C57  1uF  [SM-7351-CAP-0402]
C58  1uF  [SM-7351-CAP-0402]
C59  1uF  [SM-7351-CAP-0402]
C60  1uF  [SM-7351-CAP-0402]
C61  0.01uF  [SM-7351-CAP-0402]
C62  10uF  [SM-7351-CAP-0805]
C63  0.01uF  [SM-7351-CAP-0402]
C64  0.01uF  [SM-7351-CAP-0402]
C65  0.01uF  [SM-7351-CAP-0402]
C66  0.01uF  [SM-7351-CAP-0402]
C67  0.01uF  [SM-7351-CAP-0402]
C68  0.01uF  [SM-7351-CAP-0402]
C75  10uF  [SM-7351-CAP-0805]
C119  0.01uF  [SM-7351-CAP-0402]
C167  10uF  [SM-7351-CAP-0805]
C168  0.01uF  [SM-7351-CAP-0402]
C169  0.01uF  [SM-7351-CAP-0402]
C170  10uF  [SM-7351-CAP-0805]
C171  0.01uF  [SM-7351-CAP-0402]
C172  0.01uF  [SM-7351-CAP-0402]
C356  0.01uF  [SM-7351-CAP-0402]
C404  0.01uF  [SM-7351-CAP-0402]
C407  0.01uF  [SM-7351-CAP-0402]
C408  0.01uF  [SM-7351-CAP-0402]
C409  0.01uF  [SM-7351-CAP-0402]
C410  0.01uF  [SM-7351-CAP-0402]
C411  0.01uF  [SM-7351-CAP-0402]
C412  0.01uF  [SM-7351-CAP-0402]
C431  0.01uF  [SM-7351-CAP-0402]
C432  2.2uF  [SM-7351-CAP-0805]
C476  0.01uF  [SM-7351-CAP-0402]
FB12  150OHM800mA  [sm-7351-ind-0805]
FB13  150OHM800mA  [sm-7351-ind-0805]
FB14  150OHM800mA  [sm-7351-ind-0805]
FB15  150OHM800mA  [sm-7351-ind-0805]
FB16  150OHM800mA  [sm-7351-ind-0805]
FB17  150OHM800mA  [sm-7351-ind-0805]
FB19  150OHM800mA  [sm-7351-ind-0805]
FB20  150OHM800mA  [sm-7351-ind-0805]
FB21  150OHM800mA  [sm-7351-ind-0805]
FB22  150OHM800mA  [sm-7351-ind-0805]
J42  HEADER 4  [HDR1x4-330M]
R682  0  [SM-7351-RES-0402]
R708  0  [SM-7351-RES-0402]
R709  0  [SM-7351-RES-0402]
SCKT1  AM438X ZDN Socket  [SCKBGA625]
TP1  TP  [TH_TP_5002]
TP3  TP1mm  [tp_smd1mmcircle]
sheet Pg07: Quad SPI Memory
C124  0.01uF  [SM-7351-CAP-0402]
R154  10K  [SM-7351-RES-0402]
R155  22  [SM-7351-RES-0402]
R156  0  [SM-7351-RES-0402]
R157  0  [SM-7351-RES-0402]
R158  0  [SM-7351-RES-0402]
R159  0  [SM-7351-RES-0402]
R160  0  [SM-7351-RES-0402]
U7  MX66L51235FMI  [soic_16pin_dw]
sheet Pg09: SDMMC0 Interface
C139  0.1uF  [SM-7351-CAP-0402]
C140  4.7uF  [SM-7351-CAP-0603]
J10  MHC-W21-601  [MHC-W21-601-LF]
R196  0  [SM-7351-RES-0402]
R197  0  [SM-7351-RES-0402]
R198  10K  [SM-7351-RES-0402]
R199  10K  [SM-7351-RES-0402]
R200  10K  [SM-7351-RES-0402]
R201  10K  [SM-7351-RES-0402]
R202  10K  [SM-7351-RES-0402]
R204  0  [SM-7351-RES-0402]
R205  0  [SM-7351-RES-0402]
R206  0  [SM-7351-RES-0402]
R207  0  [SM-7351-RES-0402]
R208  0  [SM-7351-RES-0402]
R209  0  [SM-7351-RES-0402]
R210  470K  [SM-7351-RES-0402]
R211  0  [SM-7351-RES-0402]
R212  0  [SM-7351-RES-0402]
R213  0  [SM-7351-RES-0402]
R214  0  [SM-7351-RES-0402]
R652  100K  [SM-7351-RES-0402]
U10  TPD6E001  [U_10_RSE]
U11  TPD2E001  [U_5_DRL]
sheet Pg16: UART #0 RS-232
C206  0.01uF  [SM-7351-CAP-0402]
C207  10uF  [SM-7351-CAP-0805]
C208  0.1uF  [SM-7351-CAP-0402]
C209  0.1uF  [SM-7351-CAP-0402]
C210  0.1uF  [SM-7351-CAP-0402]
C211  0.1uF  [SM-7351-CAP-0402]
C477  0.01uF  [SM-7351-CAP-0402]
C478  0.01uF  [SM-7351-CAP-0402]
J19  Conn_DB9M_TH  [norcomp_db9m_th]
R343  0  [SM-7351-RES-0402]
R344  0  [SM-7351-RES-0402]
R345  0  [SM-7351-RES-0402]
R346  0  [SM-7351-RES-0402]
R563  10K  [SM-7351-RES-0402]
R564  4.7K  [SM-7351-RES-0402]
R566  0  [SM-7351-RES-0402]
R567  0  [SM-7351-RES-0402]
R688  0  [SM-7351-RES-0402]
R689  0  [SM-7351-RES-0402]
R690  0  [SM-7351-RES-0402]
R691  0  [SM-7351-RES-0402]
TP52  TP1mm  [tp_smd1mmcircle]
U21  MAX3243E  [tssop-28p-47m]
U84  SN74AVC4T245  [U_16_PW]
sheet Pg17: UART #1 RS-232
C212  0.01uF  [SM-7351-CAP-0402]
C213  10uF  [SM-7351-CAP-0805]
C214  0.1uF  [SM-7351-CAP-0402]
C215  0.1uF  [SM-7351-CAP-0402]
C216  0.1uF  [SM-7351-CAP-0402]
C217  0.1uF  [SM-7351-CAP-0402]
J20  Conn_DB9M_TH  [norcomp_db9m_th]
R348  0  [SM-7351-RES-0402]
R349  0  [SM-7351-RES-0402]
R350  0  [SM-7351-RES-0402]
R351  0  [SM-7351-RES-0402]
R352  0  [SM-7351-RES-0402]
R353  0  [SM-7351-RES-0402]
R354  0  [SM-7351-RES-0402]
R355  0  [SM-7351-RES-0402]
R356  4.7K  [SM-7351-RES-0402]
TP17  TP1mm  [tp_smd1mmcircle]
U22  MAX3243E  [tssop-28p-47m]
sheet Pg18: Wireless COM8
C219  0.01uF  [SM-7351-CAP-0402]
C230  15pF  [SM-7351-CAP-0402]
C231  2.2uF  [SM-7351-CAP-0805]
C232  1uF  [SM-7351-CAP-0402]
C391  0.01uF  [SM-7351-CAP-0402]
C392  0.01uF  [SM-7351-CAP-0402]
C393  0.01uF  [SM-7351-CAP-0402]
C394  0.01uF  [SM-7351-CAP-0402]
C395  0.01uF  [SM-7351-CAP-0402]
C396  0.01uF  [SM-7351-CAP-0402]
C397  0.01uF  [SM-7351-CAP-0402]
C398  0.01uF  [SM-7351-CAP-0402]
C399  0.01uF  [SM-7351-CAP-0402]
J21  MEC6_100pin  [MEC6-150-02-S-D-RA1]
R357  0  [SM-7351-RES-0402]
R358  0  [SM-7351-RES-0402]
R359  0  [SM-7351-RES-0402]
R360  0  [SM-7351-RES-0402]
R361  10K  [SM-7351-RES-0402]
R362  0  [SM-7351-RES-0402]
R363  0  [SM-7351-RES-0402]
R364  0  [SM-7351-RES-0402]
R365  10K  [SM-7351-RES-0402]
R366  0  [SM-7351-RES-0402]
R367  10K  [SM-7351-RES-0402]
R368  0  [SM-7351-RES-0402]
R369  0  [SM-7351-RES-0402]
R370  0  [SM-7351-RES-0402]
R371  10K  [SM-7351-RES-0402]
R372  0  [SM-7351-RES-0402]
R373  0  [SM-7351-RES-0402]
R374  10K  [SM-7351-RES-0402]
R375  0  [SM-7351-RES-0402]
R376  0  [SM-7351-RES-0402]
R377  0  [SM-7351-RES-0402]
R378  0  [SM-7351-RES-0402]
R379  0  [SM-7351-RES-0402]
R380  10K  [SM-7351-RES-0402]
R381  0  [SM-7351-RES-0402]
R382  0  [SM-7351-RES-0402]
R383  0  [SM-7351-RES-0402]
R384  57.6K  [SM-7351-RES-0402]
R385  30.1K  [SM-7351-RES-0402]
R402  0  [SM-7351-RES-0402]
R480  0  [SM-7351-RES-0402]
R545  10K  [SM-7351-RES-0402]
TP18  TP1mm  [tp_smd1mmcircle]
TP19  TP1mm  [tp_smd1mmcircle]
TP20  TP1mm  [tp_smd1mmcircle]
TP32  TP1mm  [tp_smd1mmcircle]
TP39  TP1mm  [tp_smd1mmcircle]
TP40  TP1mm  [tp_smd1mmcircle]
TP43  TP1mm  [tp_smd1mmcircle]
U27  TPS79501  [sot223_6pin]
U49  TWL1200-Q1  [TQFP7X7-48-47M]
U58  SN74AVC1T45  [smdsc70-6]
U59  SN74AVC1T45  [smdsc70-6]
sheet Pg22: SPI Interfaces
C304  0.01uF  [SM-7351-CAP-0402]
C430  0.01uF  [SM-7351-CAP-0402]
J30  HEADER 4x2  [hdr2x4-330m]
J31  HEADER 4x2  [hdr2x4-330m]
R449  0  [SM-7351-RES-0402]
R450  0  [SM-7351-RES-0402]
R550  0  [SM-7351-RES-0402]
R551  0  [SM-7351-RES-0402]
R552  0  [SM-7351-RES-0402]
R553  0  [SM-7351-RES-0402]
R554  0  [SM-7351-RES-0402]
R555  0  [SM-7351-RES-0402]
R556  0  [SM-7351-RES-0402]
R557  0  [SM-7351-RES-0402]
R558  0  [SM-7351-RES-0402]
R658  0  [SM-7351-RES-0402]
R659  0  [SM-7351-RES-0402]
R660  0  [SM-7351-RES-0402]
R661  0  [SM-7351-RES-0402]
sheet Pg23: Tamper Signals
C295  15pF  [SM-7351-CAP-0402]
C296  15pF  [SM-7351-CAP-0402]
C297  1uF  [SM-7351-CAP-0402]
J34  HEADER 10x2  [hdr2x10-330m]
J61  HEADER 2  [header_2x1]
J89  HEADER 6  [hdrtsw1x6-330m]
J94  HEADER 2  [header_2x1]
J99  CON_SMAJACK5_F  [CON_SMAJACK5_221789-1_S_S_T]
R464  0  [SM-7351-RES-0402]
R467  0  [SM-7351-RES-0402]
R468  0  [SM-7351-RES-0402]
R506  0  [SM-7351-RES-0402]
R707  0  [SM-7351-RES-0402]
R714  0  [SM-7351-RES-0402]
Y7  32.768KHz MC-306  [MC-306]
sheet Pg26: Keypad/LED's
U1  AM437X_ZDN  [AM437X_ZDN]  (sections -1,-10,-11,-12,-13,-14,-15,-16,-17,-18,-19,-2,-20,-21,-22,-23,-24,-25,-26,-27,-3,-4,-5,-6,-7,-8,-9)
sheet Pg29: Power Monitor
C312  0.1uF  [SM-7351-CAP-0402]
C313  0.1uF  [SM-7351-CAP-0402]
C314  0.01uF  [SM-7351-CAP-0402]
C315  0.1uF  [SM-7351-CAP-0402]
C316  4.7uF  [SM-7351-CAP-0603]
C319  0.1uF  [SM-7351-CAP-0402]
C320  0.01uF  [SM-7351-CAP-0402]
C321  4.7uF  [SM-7351-CAP-0603]
C322  0.1uF  [SM-7351-CAP-0402]
C351  0.1uF  [SM-7351-CAP-0402]
C352  0.1uF  [SM-7351-CAP-0402]
C466  0.1uF  [SM-7351-CAP-0402]
C467  4.7uF  [SM-7351-CAP-0603]
C468  0.01uF  [SM-7351-CAP-0402]
C470  0.1uF  [SM-7351-CAP-0402]
C471  4.7uF  [SM-7351-CAP-0603]
C472  0.01uF  [SM-7351-CAP-0402]
C473  0.1uF  [SM-7351-CAP-0402]
C474  4.7uF  [SM-7351-CAP-0603]
C475  0.01uF  [SM-7351-CAP-0402]
C481  0.1uF  [SM-7351-CAP-0402]
C482  0.1uF  [SM-7351-CAP-0402]
C483  0.01uF  [SM-7351-CAP-0402]
C484  4.7uF  [SM-7351-CAP-0603]
J39  HEADER 5  [HEADER_5X1]
J40  HEADER 2  [header_2x1]
J59  HEADER 2  [header_2x1]
J60  HEADER 2  [header_2x1]
J83  HEADER 2  [header_2x1]
J84  HEADER 2  [header_2x1]
J100  HEADER 2  [header_2x1]
J101  HEADER 2  [header_2x1]
J102  HEADER 2  [header_2x1]
R23  0.1ohm1% Sense  [SM_RES_0805_KELV]
R25  0.1ohm1% Sense  [SM_RES_0805_KELV]
R36  0.05ohm1% Sense  [SM_RES_LVK12]
R509  4.7K  [SM-7351-RES-0402]
R510  4.7K  [SM-7351-RES-0402]
R511  10K  [SM-7351-RES-0402]
R543  0.05ohm1% Sense  [SM_RES_LVK12]
R544  0.05ohm1% Sense  [SM_RES_LVK12]
R712  0.05ohm1% Sense  [SM_RES_LVK12]
U39  INA226  [MSOP3X3-10-43M]
U40  INA226  [MSOP3X3-10-43M]
U81  INA226  [MSOP3X3-10-43M]
U82  INA226  [MSOP3X3-10-43M]
U83  INA226  [MSOP3X3-10-43M]
U87  INA226  [MSOP3X3-10-43M]
sheet Pg30: GPIO Connector
C480  0.01uF  [SM-7351-CAP-0402]
J90  HEADER 12x2  [hdr2x12]
J97  CON_FLEX_40X1_FH12A-40S-0.5SH  [CON_FLEX40X1_FH12A_S_R_S]
R622  0  [SM-7351-RES-0402]
R694  1K  [SM-7351-RES-0402]
R695  1K  [SM-7351-RES-0402]
R696  1K  [SM-7351-RES-0402]
R697  1K  [SM-7351-RES-0402]
R698  1K  [SM-7351-RES-0402]
R699  1K  [SM-7351-RES-0402]
R700  1K  [SM-7351-RES-0402]
R701  1K  [SM-7351-RES-0402]
R702  1K  [SM-7351-RES-0402]
R703  0  [SM-7351-RES-0402]
R704  0  [SM-7351-RES-0402]
R705  10K  [SM-7351-RES-0402]
U86  SN74LVC1G07  [SC70-5-43M]

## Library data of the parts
C6 C9 C15 C33 C39 C42 C45 C48 C62 C75 C167 C170 C213 = 1C_10uFCapacitor16V10%0805: Cost10K: 0.04; Mistral Part No: 120011040011-R
C7 C8 C10 C11 C16 C19-C26 C28-C32 C34-C38 C40 C43 C44 C46 C47 C49-C56 C61 C63-C68 C119 C124 C168 C169 C171 C172 C212 C219 C304 C314 C320 C356 C391-C399 C404 C407-C412 C430 C431 C468 C472 C475-C478 C480 C483 = 1C_0.01uFCapacitor16V10%0402: Cost100: 0; Cost10K: 0.01; Mistral Part No: 120009030032-R
C18 C27 = 1C_22uFCapacitor16V10%0805: Mistral Part No: 120014060009-R
C57-C60 C232 = 1C_1uFCapacitor10V10%0402: Cost100: 0.33; Cost10K: 0.2; Mistral Part No: 120014050010-R
C231 C432 = 1C_2.2uF16V10%SMD0805: Cost100: 0.58; Cost10K: 0.35; Mistral Part No: 120010050002-R
FB12-FB17 FB19-FB22 = 1L_FerBead_180ohm200mA: Cost100: 0.06; Cost10K: 0.04; Mistral Part No: 130014050062-R
J42 = 2H_Header_4x1: Mistral Part No: 150014050025-R
R156-R160 R196 R197 R204-R209 R211-R214 R348-R355 R357-R360 R362-R364 R366 R368-R370 R372 R373 R375-R379 R381-R383 R402 R449 R450 R464 R467 R468 R480 R506 R550-R553 R555-R558 R622 R658-R661 R682 R688-R691 R703 R704 R708 R709 R714 = 1R_ZeroOhmResistor1_16W0402: Mistral Part No: 110014100008-R
SCKT1 = AM437X_ZDN_Processor_Socket: MfrNum: C12600; Mistral Part No: M160016080001
TP1 = 2H_TestPointThroughHole: Cost100: 0.16; Cost10K: 0.1; Mistral Part No: 160016120008-R
TP3 TP17-TP20 TP32 TP39 TP40 TP43 TP52 = 2H_Testpoint_SMD1mmCircle
R154 R199-R202 R361 R365 R367 R371 R374 R380 R511 R545 R705 = 1R_10KOhmResistor1_16W0402: Cost10K: 0; Mistral Part No: 110011060003-R
R155 = 1R_22OhmResistor1_16W1%0402: Cost100: 0.06; Cost10K: 0; DescriptiveText: RES SMD 22 OHM 1% 1/16W 0402; MfrNum: MCR01MRTF22R0; Mistral Part No: 110014060035-R
U7 = 1A_MX66L51235FMI: Mistral Part No: M141116080002
C139 C214-C217 C312 C313 C315 C319 C322 C351 C352 C466 C470 C473 C481 C482 = 1C_0.1uFCapacitor16V10%0402: Cost10K: 0.01; MfrNum: C0402C104K4RACTU; Mistral Part No: 120009030060-R
C140 = 4.7uFCapacitor6.3V20%smdX5R0603: Cost100: 0.5; Mistral Part No: 120009030426-R
J10 = 2C_Conn_SDCard_MHC-W21-601: Mistral Part No: M150016080003
R198 R563 = 1R_10KOhmResistor1_16W0402: Cost10K: 0; Loading: DNI; Mistral Part No: 110011060003-R
R210 = 470Kohm1_16W1%SMD0402: Cost100: 0.01; Cost10K: 0; Mistral Part No: 110014060044-R
R652 = 1R_100KOhmResistor1_16W0402: Cost100: 0.01; Cost10K: 0; Mistral Part No: 110014060043-R
U10 = 1A_TPD6E001RSE: MfrNum: TPD6E001RSER; Mistral Part No: 141011080020
U11 = 1A_TPD2E001DRL: MfrNum: TPD2E001DRLR; Mistral Part No: M130016080007
C206 = 1C_0.01uFCapacitor16V10%0402: Cost100: 0; Cost10K: 0.01; Loading: DNI; Mistral Part No: 120009030032-R
C207 = 1C_10uFCapacitor16V10%0805: Cost10K: 0.04; Loading: DNI; Mistral Part No: 120011040011-R
C208-C211 = 1C_0.1uFCapacitor16V10%0402: Cost10K: 0.01; Loading: DNI; MfrNum: C0402C104K4RACTU; Mistral Part No: 120009030060-R
J19 = 2C_Conn_DSUB9M_TH: Cost100: 1.2; Loading: DNI; Mistral Part No: 150009030096-R
R343-R346 R554 R566 R567 R707 = 1R_ZeroOhmResistor1_16W0402: Loading: DNI; Mistral Part No: 110014100008-R
R356 R564 = 1R_4.7KOhmResistor1_16W0402: Cost100: 0; Cost10K: 0.02; Loading: DNI; Mistral Part No: 110014060028-R
U21 = 1A_MAX3243E: Loading: DNI; MfrNum: MAX3243ECPWR; Mistral Part No: M141016080002
U84 = 1A_SN74AVC4T245: MfrNum: SN74AVC4T245PWR; Mistral Part No: 141009030111-R
J20 = 2C_Conn_DSUB9M_TH: Cost100: 1.2; Mistral Part No: 150009030096-R
U22 = 1A_MAX3243E: MfrNum: MAX3243ECPWR; Mistral Part No: M141016080002
C230 C295 C296 = 1C_15pFCapacitor50V10%smd0402: Cost100: 0.01; Cost10K: 0; Mistral Part No: 120009030233-R
J21 = 2C_Conn_SamtecMEC6_150: Mistral Part No: 150014050030-R
R384 = 1R_57.6Kohm1_10W1%smd0402: Cost100: 0.04; Cost10K: 0; Mistral Part No: M110016080007
R385 = 1R_30.1Kohm1_16W1%smd0402: Cost100: 0; Cost10K: 0; Mistral Part No: 110014060033-R
U27 = 1A_TPS79501: Cost100: 2; Cost10K: 0.6; MfrNum: TPS79501DCQR; Mistral Part No: 142009030419-R
U49 = 1A_TWL1200-Q1: Mistral Part No: 141014060024-R
U58 U59 = 1A_SN74AVC1T45: MfrNum: SN74AVC1T45DCKR; Mistral Part No: 141009030020-R
J30 J31 = 2H_Header4x2: Cost100: 0.62; Cost10K: 0.62; Mistral Part No: M150016080007
C297 = 1C_1uFCapacitor10V10%0402: Cost100: 0.33; Cost10K: 0.2; Loading: DNI; Mistral Part No: 120014050010-R
J34 = 2H_Header10x2: Cost100: 1.2; Cost10K: 0.97; DescriptiveText: Dual Line Header 10x2pin 0.1in pitch; Mistral Part No: 150014050024-R; PartName: HEADERARMJTAG10x2Pin; TIIntPartnumber: 2H0074
J40 J59-J61 J83 J84 J94 J100-J102 = 2H_Header_2x1: Cost100: 0.01; Cost10K: 0.25; Mistral Part No: M150016080001
J89 = 2H_Header_6x1: Cost100: 0.32; Cost10K: 0.61; Mistral Part No: 150016060022-R
J99 = CON_SMAJACK5_F: Chkd/date: NAVEED/031014; Composition: Updated drill size; Crtd /date: VASANTHA/240714; Custom_Duty: 24%; Customs_HS_Code: 85369090; DescriptiveText: CON SMA JACK 5POS FEMALE ST TH; Distributor_name: DIGIKEY; Distributor_part_number: ACX1962-ND; Loading: DNI; Mfr: TYCO ELECTRONICS; MfrNum: 221789-1; Mistral Part No: 150011080043-R; Package: THRU HOLE; PartName: 221789-1; Part_type: CONNECTOR\JACK; Project: DC_MIST_RF-TEST CARD; RoHS: RoHS; Temperature: NA; Tolerance: NA; Vendor: Digikey; Voltage: NA; Wattage: NA; Weight: NA; Datasheet: Y:\MIS_DATABASE\DATASHEETS\CONNECTORS\132134-15.PDF
Y7 = 1Y_Crystal_SMD32_768kHz: Cost10K: 0.33; MfrNum: MC-306 32.7680K-A0:ROHS; Mistral Part No: M130016080010
U1 = am438x_ZDN_ePOS_EVM_13: MfrNum: XAM4384CZDNA100S; Mistral Part No: 141214060001
C316 C321 C467 C471 C474 C484 = 4.7uFCapacitor16V10%0603: Cost100: 0.01; Cost10K: 0; Mistral Part No: 120011050004-R
J39 = 2H_Header_5x1: Cost100: 0.32; Cost10K: 0.29; Mistral Part No: 150014050023-R
R23 R25 = 1R_0.1ohm0.33W1%Sense0805: Mistral Part No: M110016080001
R36 R543 R544 R712 = 1R_0.05ohm0.5W1%Sense1206: Mistral Part No: M110016080002
R509 R510 = 1R_4.7KOhmResistor1_16W0402: Cost100: 0; Cost10K: 0.02; Mistral Part No: 110014060028-R
U39 U40 U81-U83 U87 = 1A_INA226: Cost10K: 1.72; MfrNum: INA226AIDGSR; Mistral Part No: 141011080019-R
J90 = 2H_Header12x2: Cost10K: 0.57; Mistral Part No: 150014050022-R
J97 = CON_FLEX_40X1_FH12A-40S-0.5SH: CON FPC 40X1 0.50MM PITCH RT TOP SMD; Chkd/date: SHREESHAIL/201106; Composition: CON_FLEX40X1_FH12A_S_R_S_PMP take this footprint for PMP LCD BOARD/ROHS INFORMATION ADDED(BAVISH/270911)Mistral part# updated with -R.; Crtd /date: MAZHAR/171106; Custom_Duty: 24%; Customs_HS_Code: 85369090; DescriptiveText: CON FPC 40X1 0.50MM PITCH RT TOP SMD; Distributor_name: DIGIKEY; Distributor_part_number: HFK40CT-ND; Mfr: HIROSE ELECTRIC EUROPE; MfrNum: FH12A-40S-0.5SH(55); Mfr_name: HIROSE ELECTRIC EUROPE; Mfr_part_number: FH12A-40S-0.5SH(55); Mistral Part No: 150009030176-R; Package: SMD; Part_type: CONNECTOR\FPC; Project: PMP LCD BOARD; Datasheet: Y:\MIS_DATABASE\DATASHEETS\CONNECTORS\FH12SERIES.PDF
R694-R702 = 1R_1KOhmResistor1_16W0402: Cost100: 0.02; Cost10K: 0.02; Mistral Part No: 110009030400-R
U86 = 1A_SN74LVC1G07: MfrNum: SN74LVC1G07DCKR; Mistral Part No: 141014060023-R

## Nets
DGND: C6.2 C7.2 C8.2 C9.2 C10.2 C11.2 C15.2 C16.2 C18.2 C19.2 C20.2 C21.2 C22.2 C23.2 C24.2 C25.2 C26.2 C27.2 C28.2 C29.2 C30.2 C31.2 C32.2 C33.2 C34.2 C35.2 C36.2 C37.2 C38.2 C39.2 C40.2 C42.2 C43.2 C44.2 C45.2 C46.2 C47.2 C48.2 C49.2 C50.2 C51.2 C52.2 C55.2 C56.2 C57.2 C58.2 C59.2 C60.2 C61.2 C62.2 C63.2 C64.2 C65.2 C66.2 C67.2 C68.2 C75.2 C119.2 C124.2 C139.2 C140.2 C167.2 C168.2 C169.2 C170.2 C171.2 C172.2 C206.2 C207.2 C209.2 C211.2 C212.2 C213.2 C215.2 C217.2 C219.2 C231.2 C232.2 C295.2 C296.2 C297.2 C304.2 C314.2 C315.2 C316.2 C320.2 C321.2 C322.2 C356.2 C391.2 C392.2 C393.2 C394.2 C395.2 C396.2 C397.2 C398.2 C399.2 C404.2 C407.2 C408.2 C409.2 C410.2 C411.2 C412.2 C430.2 C431.2 C432.2 C466.2 C467.2 C468.2 C470.2 C471.2 C472.2 C473.2 C474.2 C475.2 C476.2 C477.2 C478.2 C480.2 C482.2 C483.2 C484.2 J10.3(#3_MMC+/MMCM/RSMMC/MMC/SD) J10.6(#6_MMC+/MMCM/RSMMC/MMC/SD) J10.18(#3_miniSD) J10.21(#6_miniSD) J10.27(GND1) J10.28(GND2) J19.5 J19.10 J19.11 J20.5 J20.10 J20.11 J21.2 J21.3 J21.6 J21.9 J21.18 J21.19 J21.22 J21.35 J21.37 J21.39 J21.42 J21.47 J21.60 J21.63 J21.64 J21.77 J21.83 J21.87 J21.92 J21.95 J21.97 J30.2 J30.7 J31.2 J31.7 J34.3 J34.20 J39.3 J42.1 J61.2 J89.1 J89.2 J89.3 J89.4 J89.5 J89.6 J90.13 J90.16 J90.23 J97.7 J97.16 J97.25 J97.34 J97.40 J97.41 J97.42 J99.2 J99.3 J99.4 J99.5 R356.1(P1) R385.1(P1) R480.2(P2) R545.1(P1) R564.1(P1) R566.1(P1) R567.1(P1) R652.1(P1) R682.1(P1) U1.A1(GND) U1.A25(GND) U1.AA23(TEST_EN) U1.AE1(GND) U1.AE25(GND) U1.F8(VDDA3P3_PMLDO) U1.H15(GND) U1.H18(GND) U1.J9(GND) U1.J12(GND) U1.J15(GND) U1.J17(GND) U1.K9(GND) U1.K11(GND) U1.K12(GND) U1.K14(GND) U1.K15(GND) U1.L8(GND) U1.L9(GND) U1.L11(GND) U1.L15(GND) U1.L17(GND) U1.L18(GND) U1.M10(GND) U1.M11(GND) U1.M13(GND) U1.M15(GND) U1.M16(GND) U1.N10(GND) U1.N11(GND) U1.N12(GND) U1.N13(GND) U1.N14(GND) U1.N15(GND) U1.P8(GND) U1.P9(GND) U1.P10(GND) U1.P11(GND) U1.P12(GND) U1.P13(GND) U1.P14(GND) U1.P15(GND) U1.R12(GND) U1.R15(GND) U1.R17(GND) U1.R18(GND) U1.T12(GND) U1.T15(GND) U1.T17(GND) U1.U8(GND) U1.U9(GND) U1.U10(GND) U1.U11(GND) U1.U12(GND) U1.U13(GND) U1.U14(GND) U1.U16(GND) U1.U17(GND) U1.U18(GND) U1.U19(GND) U1.V9(GND) U1.V10(GND) U1.V11(GND) U1.V12(GND) U1.V13(GND) U1.V14(GND) U1.V18(GND) U1.W23(VSSA_USB) U7.10(GND) U10.5(GND) U11.4(GND) U21.25(GND) U22.25(GND) U27.3(GND) U27.6(GND) U39.1(A1) U39.2(A0) U39.7(GND) U40.1(A1) U40.7(GND) U49.8(GND) U49.14(GND) U49.20(GND) U49.26(GND) U58.2(GND) U59.2(GND) U59.5(DIR) U81.1(A1) U81.7(GND) U82.1(A1) U82.7(GND) U83.2(A0) U83.7(GND) U84.3(2DIR) U84.8(GND) U84.9(GND) U84.14(2~{OE}) U84.15(1~{OE}) U86.3(GND) U87.7(GND) ; also on sheet 1 2 4 5 7 8 9 10 11 13 14 15 16 27 28 30 31
GND_OSC: U1.B24(VSS_OSC) ; also on sheet 31
GNDA_ADC: C53.2 C54.2 R682.2(P2) U1.AC15(VSSA_ADC) ; also on sheet 1 3 6
V1_0BAT: C55.1 U1.AD9(VDD_TPM) ; also on sheet 30
V1_8BAT: C56.1 J34.1 U1.AD8(VDDS_TPM) ; also on sheet 30
V1_8D: C392.1 C394.1 C395.1 C397.1 C399.1 C470.1 J21.8 J21.62 R23.1(I1) R361.2(P2) R365.2(P2) R367.2(P2) R371.2(P2) R374.2(P2) R380.2(P2) R383.2(P2) U49.32(VCCB) U49.38(VCCB) U58.1(VCCA) U58.5(DIR) U59.1(VCCA) U82.8(VBUS) ; also on sheet 2 3 30
V3_3D: C124.1 C206.1 C207.1 C212.1 C213.1 C314.1 C316.1 C320.1 C321.1 C391.1 C393.1 C396.1 C398.1 C467.1 C468.1 C471.1 C472.1 C473.1 C474.1 C475.1 C477.1 C480.1 C483.1 C484.1 J34.2 J42.3 J90.2 J97.1 J97.2 J97.3 R25.1(I1) R154.2(P2) R196.2(P2) R197.2(P2) R210.2(P2) R213.2(P2) R214.2(P2) R449.1(P1) R450.1(P1) R509.2(P2) R510.2(P2) R511.2(P2) R563.2(P2) R705.2(P2) U7.2(VCC) U21.26(VCC) U22.26(VCC) U39.6(VS) U40.2(A0) U40.6(VS) U49.2(VCCA) U49.44(VCCA) U58.6(VCCB) U59.6(VCCB) U81.6(VS) U82.6(VS) U83.1(A1) U83.6(VS) U83.8(VBUS) U84.1(VCCA) U84.2(1DIR) U86.5(VCC) U87.1(A1) U87.2(A0) U87.6(VS) ; also on sheet 1 2 4 5 7 8 9 10 11 13 15 27 28 30 31
V3_3D_AM438X: C6.1 C7.1 C8.1 C9.1 C10.1 C11.1 C15.1 C16.1 C33.1 C34.1 C35.1 C36.1 C37.1 C38.1 C39.1 C40.1 C42.1 C43.1 C44.1 C45.1 C46.1 C47.1 C75.1 C119.1 C167.1 C168.1 C169.1 C170.1 C171.1 C172.1 C412.1 R25.2(I2) U1.F16(VDDSHV7) U1.F22(VDDSHV5) U1.G10(VDDSHV10) U1.G11(VDDSHV9) U1.G13(VDDSHV8) U1.G14(VDDSHV8) U1.G16(VDDSHV6) U1.G17(VDDSHV6) U1.H8(VDDSHV11) U1.H9(VDDSHV11) U1.H10(VDDSHV10) U1.H11(VDDSHV9) U1.H17(VDDSHV6) U1.J7(VDDSHV1) U1.J8(VDDSHV1) U1.J18(VDDSHV3) U1.K17(VDDSHV3) U1.K18(VDDSHV3) U1.N18(VDDSHV3) U1.N19(VDDSHV3) U1.P18(VDDSHV3) U1.U20(VDDA_3P3V_USB1) U1.V16(VDDSHV2) U1.V17(VDDSHV2) U1.W16(VDDSHV2) U1.W18(VDDSHV3) U1.W20(VDDA_3P3V_USB0)
V3_3FTDI: C478.1 U84.16(VCCB) ; also on sheet 8
VBAT: C232.1 J90.1 J90.3 U27.2(IN) ; also on sheet 1 2 4 5 7 14 15 16 28 30
VDD_CORE: C18.1 C19.1 C20.1 C21.1 C22.1 C23.1 C24.1 C25.1 C26.1 C60.1 R543.2(I2) U1.AD3(CAP_VDD_RTC) U1.J10(VDD_CORE) U1.J11(VDD_CORE) U1.L12(VDD_CORE) U1.L14(VDD_CORE) U1.M9(VDD_CORE) U1.M12(VDD_CORE) U1.M14(VDD_CORE) U1.N9(VDD_CORE) U1.N16(VDD_CORE) U1.N17(VDD_CORE) U1.P16(VDD_CORE) U1.P17(VDD_CORE) U1.R9(VDD_CORE) U1.R11(VDD_CORE) U1.R14(VDD_CORE) U1.T9(VDD_CORE) U1.T11(VDD_CORE) U1.T14(VDD_CORE) U1.T18(VDD_CORE) U1.T19(VDD_CORE) U1.U15(VDD_CORE) U1.V15(VDD_CORE) U1.W12(VDD_CORE) U1.W13(VDD_CORE)
VDD_MPU: C27.1 C28.1 C29.1 C30.1 C31.1 C32.1 R544.2(I2) U1.H13(VDD_MPU) U1.H14(VDD_MPU) U1.H16(VDD_MPU) U1.J13(VDD_MPU) U1.J14(VDD_MPU) U1.J16(VDD_MPU) U1.K19(VDD_MPU) U1.K20(VDD_MPU) U1.L19(VDD_MPU) U1.L20(VDD_MPU) U1.M17(VDD_MPU) U1.M18(VDD_MPU)
VDDA1_8_USB0: C411.1 C432.1 FB14.2 U1.W21(VDDA1P8V_USB0)
VDDA_ADC: C53.1 FB22.1 U1.AB12(VDDA_TS_ADC) ; also on sheet 1 3
VDDA_MAGADC: C54.1 FB21.1 U1.Y16(VDDA_MC_ADC) ; also on sheet 6
VDDS_CTM: FB13.1 FB15.1 FB16.1 FB17.1 FB19.1 FB20.1 U1.AD12(VDDS_CTM)
VDDS_DDR: R712.1(I1) ; also on sheet 16
VDDS_PLL_CORE_LCD: C410.1 FB16.2 U1.N21(VDDS_PLL_CORE_LCD)
VDDS_PLL_DDR: C409.1 FB15.2 U1.G5(VDDS_PLL_DDR)
VDDS_PLL_MPU: C404.1 FB17.2 U1.E17(VDDS_PLL_MPU)
VDDS_SRAM_CORE_BG: C408.1 FB19.2 U1.F13(VDDS_SRAM_CORE_BG)
VDDS_SRAM_MPU_BB: C407.1 FB20.2 U1.F14(VDDS_SRAM_MPU_BB)
AM438X_CAM1_DATA0: R351.2(P2) ; also on sheet 7
AM438X_CAM1_DATA1: R348.2(P2) ; also on sheet 7
AM438X_CAM1_DATA2: R355.2(P2) ; also on sheet 7
AM438X_CAM1_DATA3: R349.2(P2) ; also on sheet 7
AM438X_CAM1_DATA4: R352.2(P2) ; also on sheet 7
AM438X_CAM1_DATA5: R353.2(P2) ; also on sheet 7
AM438X_CAM1_DATA6: R354.2(P2) ; also on sheet 7
AM438X_CAM1_DATA7: R350.2(P2) ; also on sheet 7
AM438X_COM_BTRST: U1.E7(GPMC_A5/GPIO) U49.10(BT_ENA)
AM438X_COM_PPSOUT: U1.D7(GPMC_A4/GPIO) U58.4(B)
AM438X_COM_TIMESTAMP: U1.E8(GPMC_A6/GPIO) U59.4(B)
AM438X_COM_WLRST: U1.F6(GPMC_A7/GPIO) U49.7(WLAN_ENA)
AM438X_GPMC_ADVN_ALE: R156.2(P2) ; also on sheet 27
AM438X_GPMC_BE0N_CLE: R159.2(P2) ; also on sheet 27
AM438X_GPMC_CS0n: R160.2(P2) ; also on sheet 27
AM438X_GPMC_OEN_REN: R157.2(P2) ; also on sheet 27
AM438X_GPMC_WEN: R158.2(P2) ; also on sheet 27
AM438X_GPMC_WPn: R402.1(P1) U1.B3(GPMC_WPn/GPIO) ; also on sheet 27
AM438X_I2C0_SCL: J101.1 ; also on sheet 30
AM438X_I2C0_SDA: J102.1 ; also on sheet 30
AM438X_LCD_AC_BIAS_EN: R702.2(P2) ; also on sheet 4 5 11
AM438X_LCD_DATA0: R694.2(P2) ; also on sheet 4 5 11
AM438X_LCD_DATA1: R695.2(P2) ; also on sheet 4 5 11
AM438X_LCD_DATA2: R696.2(P2) ; also on sheet 4 5 11
AM438X_LCD_DATA3: R697.2(P2) ; also on sheet 4 5 11
AM438X_LCD_DATA4: R698.2(P2) ; also on sheet 4 5 11
AM438X_LCD_DATA6: R699.2(P2) ; also on sheet 4 5 11
AM438X_LCD_DATA7: R700.2(P2) ; also on sheet 4 5 11
AM438X_LCD_HSYNC: R701.2(P2) ; also on sheet 4 5 11
AM438X_MMC0_CLK: R206.2(P2) U1.D1(MMC0_CLK)
AM438X_MMC0_CMD: R205.2(P2) U1.D2(MMC0_CMD)
AM438X_MMC0_DAT0: R207.2(P2) U1.C1(MMC0_DAT0)
AM438X_MMC0_DAT1: R208.2(P2) U1.C2(MMC0_DAT1)
AM438X_MMC0_DAT2: R209.2(P2) U1.B2(MMC0_DAT2)
AM438X_MMC0_DAT3: R204.2(P2) U1.B1(MMC0_DAT3)
AM438X_PMIC_IN_nCC: R506.1(P1) ; also on sheet 30
AM438X_PMIC_PGOOD: R704.2(P2) ; also on sheet 30 31
AM438X_PMU_PORZn: R467.2(P2) U1.AE10(PMU_PORZ)
AM438X_POWER_EN1: R468.2(P2) U1.AD7(TPM_PMIC_EN)
AM438X_QSPI_CLK: R155.2(P2) U1.B12(GPMC_CSN3/QSPI_CLK)
AM438X_SPI0_CS0: R553.2(P2) U1.T20(SPI0_CS0)
AM438X_SPI0_DIN: R552.2(P2) U1.T21(SPI0_D1)
AM438X_SPI0_DOUT: R551.2(P2) U1.T22(SPI0_D0)
AM438X_SPI0_SCLK: R550.2(P2) U1.P23(SPI0_SCLK)
AM438X_SPI1_CS0n: R558.1(P1) R661.2(P2) U1.M24(MCASP0_AHCLKR/SPI1_CS0n)
AM438X_SPI1_D0: R556.2(P2) R659.2(P2) U1.N22(MCASP0_FSX/SPI1_D0)
AM438X_SPI1_D1: R557.1(P1) R660.2(P2) U1.H23(MCASP0_AXR0/SPI1_D1)
AM438X_SPI1_SCLK: R555.2(P2) R658.2(P2) U1.N24(MCASP0_ACLKX/SPI1_SCLK)
AM438X_STATUS_LED1: R554.1(P1) ; also on sheet 14 28
AM438X_UART0_CTSn: R345.2(P2) R691.1(P1) U1.L25(UART0_CTSn)
AM438X_UART0_RTSn: R346.2(P2) R689.1(P1) U1.J25(UART0_RTSn)
AM438X_UART0_RXD: R344.2(P2) R690.1(P1) U1.K25(UART0_RXD)
AM438X_UART0_TXD: R343.2(P2) R688.1(P1) U1.J24(UART0_TXD)
AM438X_UART3_RTSN: U1.K24(UART3_RTSn) U49.11(UART_CTSA) ; also on sheet 30
AM438X_VDDS: C48.1 C49.1 C50.1 C51.1 C52.1 C61.1 C356.1 C431.1 FB12.1 FB13.2 FB14.1 FB21.2 FB22.2 R23.2(I2) U1.AD5(VDDS_RTC) U1.C23(VDDS_OSC) U1.F20(VDDS) U1.G6(VDDS) U1.H12(VDDS) U1.P19(VDDS) U1.U21(VDDA1P8V_USB1) U1.W15(VDDS) U1.Y19(VDDS) ; also on sheet 31
AM438X_WAKEUP1: U1.AE7(TPM_WAKEUP) ; also on sheet 30
AM438X_XI_32K: R707.1(P1) R714.2(P2) U1.AE11(XI_32K)
AM438X_XO_32K: R464.1(P1) U1.AE12(XO_32K)
CAP_VBB_MPU: C57.1 U1.F19(CAP_VBB_MPU)
CAP_VDD_SRAM_CORE: C59.1 U1.E13(CAP_VDD_SRAM_CORE)
CAP_VDD_SRAM_MPU: C58.1 U1.E14(CAP_VDD_SRAM_MPU)
COM_AUD_CLK: J21.52 R379.2(P2)
COM_AUD_FSYNC: J21.54 R359.2(P2)
COM_AUD_IN: J21.56 R364.2(P2)
COM_AUD_OUT: J21.58 R372.2(P2)
COM_BTRST: J21.89 R382.1(P1)
COM_BTUARTCTS: J21.70 R369.2(P2)
COM_BTUARTDEBUG: J21.76 TP32.1
COM_BTUARTRTS: J21.72 R376.2(P2)
COM_BTUARTRX: J21.68 R377.2(P2)
COM_BTUARTTX: J21.66 R363.2(P2)
COM_GNSS_PPS_OUT: J21.50 R370.2(P2)
COM_GNSS_TIME_STAMP: J21.48 R360.2(P2)
COM_SDIO_CLK: J21.20 R365.1(P1) R378.2(P2)
COM_SDIO_CMD: J21.24 R357.2(P2) R371.1(P1)
COM_SDIO_D0: J21.26 R368.2(P2) R380.1(P1)
COM_SDIO_D1: J21.28 R361.1(P1) R375.2(P2)
COM_SDIO_D2: J21.30 R367.1(P1) R381.2(P2)
COM_SDIO_D3: J21.32 R362.2(P2) R374.1(P1)
COM_SLOW_CLK: J21.1 R358.1(P1)
COM_WL_IRQ: J21.34 R373.2(P2)
COM_WL_RS232_RX: J21.13 TP19.1
COM_WL_RS232_TX: J21.11 TP18.1
COM_WL_RST: J21.4 R366.2(P2)
COM_WL_UART_DBG: J21.15 TP20.1
FTDI_BDBUS0_TXD: U84.11(2B1) ; also on sheet 8
FTDI_BDBUS1_RXD: U84.13(1B1) ; also on sheet 8
FTDI_BDBUS2_RTSn: U84.10(2B2) ; also on sheet 8
FTDI_BDBUS3_CTSn: U84.12(1B2) ; also on sheet 8
MMC0_CD: J10.15(CD) R210.1(P1) R212.1(P1) U11.3(IO1)
MMC0_CLK: J10.5(#5_MMC+/MMCM/RSMMC/MMC/SD) J10.20(#5_miniSD) R206.1(P1) U10.1(IO1)
MMC0_CMD: J10.2(#2_MMC+/MMCM/RSMMC/MMC/SD) J10.17(#2_miniSD) R199.1(P1) R205.1(P1) U10.7(IO5)
MMC0_D0: J10.7(#7_MMC+/MMCM/RSMMC/MMC/SD) J10.22(#7_miniSD) R200.1(P1) R207.1(P1) U10.2(IO2)
MMC0_D1: J10.8(#8_MMC+/MMCM/SD) J10.23(#8_miniSD) R201.1(P1) R208.1(P1) U10.3(IO3)
MMC0_D2: J10.9(#9_MMC+/MMCM/SD) J10.24(#9_miniSD) R202.1(P1) R209.1(P1) U10.6(IO4)
MMC0_D3: J10.1(#1_MMC+/MMCM/RSMMC/MMC/SD) J10.16(#1_miniSD) R198.1(P1) R204.1(P1) R652.2(P2) U10.8(IO6)
MMC0_WP: J10.14(SD_WP) R211.1(P1) U11.5(IO2)
PM_ALERT: J39.4 R511.1(P1) U39.3(ALERT) U40.3(ALERT) U81.3(ALERT) U82.3(ALERT) U83.3(ALERT) U87.3(ALERT)
PM_AM438X_V1_8DN: C351.2 J83.2 R23.4(SENS2) U82.9(VIN-)
PM_AM438X_V1_8DP: C351.1 J83.1 R23.3(SENS1) U82.10(VIN+)
PM_AM438X_V3_3DN: C352.2 J84.2 R25.4(SENS2) U83.9(VIN-)
PM_AM438X_V3_3DP: C352.1 J84.1 R25.3(SENS1) U83.10(VIN+)
PM_LPDDR2N: C481.2 J100.2 R712.3(SENS1) U87.9(VIN-)
PM_LPDDR2P: C481.1 J100.1 R712.4(SENS2) U87.10(VIN+)
PM_VDDCOREN: C312.2 J59.2 R543.4(SENS2) U39.9(VIN-)
PM_VDDCOREP: C312.1 J59.1 R543.3(SENS1) U39.10(VIN+)
PM_VDDMPUN: C319.2 J60.2 R544.4(SENS2) U40.9(VIN-)
PM_VDDMPUP: C319.1 J60.1 R544.3(SENS1) U40.10(VIN+)
PM_VDDSDDRN: C313.2 J40.2 R36.4(SENS2) U81.9(VIN-)
PM_VDDSDDRP: C313.1 J40.1 R36.3(SENS1) U81.10(VIN+)
PMIC_PWR_EN: R468.1(P1) ; also on sheet 30
PMU_PORZn: C297.1 J61.1 R467.1(P1) ; also on sheet 30
PRINT_eHRPWM0_A: J90.4 R658.1(P1)
PRINT_eHRPWM0_B: J90.6 R659.1(P1)
PRINT_eHRPWM1_A: J90.12 ; also on sheet 28
PRINT_eHRPWM1_B: J90.14 ; also on sheet 28
PRINT_SPI_CLK: J90.15 ; also on sheet 28
PRINT_SPI_CSn: J90.17 ; also on sheet 28
PRINT_SPI_MISO: J90.21 ; also on sheet 28
PRINT_SPI_MOSI: J90.19 ; also on sheet 28
PRINT_SYNCI: J90.10 R661.1(P1)
PRINT_TRIPZONE: J90.8 R660.1(P1)
PRINTER_GPIO0: J90.11 ; also on sheet 28
PRINTER_GPIO1: J90.9 ; also on sheet 1
PRINTER_GPIO2: J90.7 ; also on sheet 1
PRINTER_GPIO3: J90.5 ; also on sheet 13
PWRMON_I2CSCL: J39.1 J97.36 J101.2 R509.1(P1) U39.5(SCL) U40.5(SCL) U81.5(SCL) U82.2(A0) U82.5(SCL) U83.5(SCL) U87.5(SCL)
PWRMON_I2CSDA: J39.2 J97.38 J102.2 R510.1(P1) U39.4(SDA) U40.4(SDA) U81.2(A0) U81.4(SDA) U82.4(SDA) U83.4(SDA) U87.4(SDA)
RESERVED1: J34.9 U1.AA9(RESERVED1)
RESERVED3: J34.15 U1.AC5(RESERVED3)
RESERVED4: J34.16 U1.AB7(RESERVED4)
RESERVED5: J34.4 U1.AB6(RESERVED5)
RS232_0_CTS: J19.8 U21.5(RIN2)
RS232_0_RTS: J19.7 U21.10(DOUT2)
RS232_0_RXD: J19.2 U21.4(RIN1)
RS232_0_TXD: J19.3 U21.9(DOUT1)
RS232_1_CTS: J20.8 U22.8(RIN5)
RS232_1_DCD: J20.1 U22.7(RIN4)
RS232_1_DSR: J20.6 U22.6(RIN3)
RS232_1_DTR: J20.4 U22.11(DOUT3)
RS232_1_EN: R356.2(P2) U22.22(~{FOFF}) U22.23(FON) ; also on sheet 7 28
RS232_1_RI: J20.9 U22.5(RIN2)
RS232_1_RTS: J20.7 U22.10(DOUT2)
RS232_1_RXD: J20.2 U22.4(RIN1)
RS232_1_TXD: J20.3 U22.9(DOUT1)
RTC_ALARM: J34.19 U1.C13(GMII1_TXD2/RTC_ALARM)
SDMMC0_WP: R211.2(P2) ; also on sheet 28
SPIMEM_CLK: R155.1(P1) U7.16(SCLK)
SPIMEM_CS: R160.1(P1) U7.7(~{CS})
SPIMEM_D0: R156.1(P1) U7.15(SI/SIO0)
SPIMEM_D1: R157.1(P1) U7.8(SO/SIO1)
SPIMEM_D2: R154.1(P1) R158.1(P1) U7.9(~{WP}/SIO2)
SPIMEM_D3: R159.1(P1) U7.1(DNU/SIO3)
SYS_RESETn: U7.3(~{RESET}) ; also on sheet 2 4 9 11 31
SYS_WARMRESETn: R703.1(P1) ; also on sheet 8 31
TEST_GPIO17: R622.2(P2) ; also on sheet 28
TEST_PORZn: J97.27 R705.1(P1) U86.2(A)
TM_PIO_0: J34.5 U1.AC12(TM_PIO_0/GPIO)
TM_PIO_1: J34.6 U1.AC10(TM_PIO_1/GPIO)
TM_PIO_2: J34.7 U1.AB10(TM_PIO_2/GPIO)
TM_PIO_3: J34.8 U1.AA10(TM_PIO_3/GPIO)
TM_PIO_8: J34.11 U1.AC9(TM_PIO_8/GPIO)
TM_PIO_9: J34.12 U1.Y7(TM_PIO_9/GPIO)
TM_PIO_10: J34.13 U1.AA7(TM_PIO_10/GPIO)
TM_PIO_11: J34.14 U1.AC6(TM_PIO_11/GPIO)
TPMSS_OUT: J34.10 U1.Y10(RESERVED2/TPMSS_OUT)
UART0_CTSn: R345.1(P1) U21.18(ROUT2)
UART0_RTSn: R346.1(P1) U21.13(DIN2)
UART0_RXD: R344.1(P1) U21.19(ROUT1)
UART0_TXD: R343.1(P1) U21.14(DIN1)
UART1_CTSn: R355.1(P1) U22.15(ROUT5)
UART1_DCD: R354.1(P1) U22.16(ROUT4)
UART1_DSR: R353.1(P1) U22.17(ROUT3)
UART1_DTR: R350.1(P1) U22.12(DIN3)
UART1_RI: R352.1(P1) U22.20(ROUT2B)
UART1_RTSn: R349.1(P1) U22.13(DIN2)
UART1_RXD: R351.1(P1) U22.19(ROUT1)
UART1_TXD: R348.1(P1) U22.14(DIN1)
VAM438X_DDR: C62.1 C63.1 C64.1 C65.1 C66.1 C67.1 C68.1 R36.2(I2) U1.K7(VDD_DDR) U1.K8(VDD_DDR) U1.M7(VDD_DDR) U1.M8(VDD_DDR) U1.N7(VDD_DDR) U1.N8(VDD_DDR) U1.R6(VDD_DDR) U1.R7(VDD_DDR) U1.R8(VDD_DDR) U1.T7(VDD_DDR) U1.T8(VDD_DDR) U1.V7(VDD_DDR) U1.V8(VDD_DDR) ; also on sheet 16
VCOM_BAT: C219.1 C230.1 C231.1 J21.5 J21.7 R384.2 U27.4(OUT)
VCOM_BATEN: R383.1(P1) U27.1(EN)
VCOM_BATFB: C230.2 R384.1 R385.2(P2) U27.5(FB)
VDCDC1: C315.1 R543.1(I1) U39.8(VBUS) ; also on sheet 30
VDCDC2: C322.1 R544.1(I1) U40.8(VBUS) ; also on sheet 30
VDCDC3: C482.1 R712.2(I2) U87.8(VBUS) ; also on sheet 30
VLS1: C466.1 R36.1(I1) U81.8(VBUS) ; also on sheet 30
VMMC0_0: R196.1(P1) R198.2(P2) R199.2(P2) R200.2(P2) R201.2(P2) R202.2(P2)
VMMC0_1: C139.1 C140.1 J10.4(#4_MMC+/MMCM/RSMMC/MMC/SD) J10.19(#4_miniSD) R197.1(P1)
VMMC0_2: R213.1(P1) U10.10(VCC)
VMMC0_3: R214.1(P1) U11.1(VCC)
VPP_CONN: J42.2 R708.1(P1)
VPP_CTRL: R709.2(P2) ; also on sheet 28
N12772991: R358.2(P2) U49.18(SLOWCLKB)
N12773186: R382.2(P2) U49.28(BT_ENB)
N13826777: C214.2 U22.24(C1-)
N13826781: C216.1 U22.1(C2+)
N13826785: C216.2 U22.2(C2-)
N13826789: C214.1 U22.28(C1+)
N13826859: C217.1 U22.3(V-)
N13826863: C215.1 U22.27(V+)
N13827073: TP17.1 U22.21(~{INVALID})
N13891683: C296.1 R464.2(P2) Y7.4
N13891751: R506.2(P2) U1.AE8(PMU_HIBZ)
N14123912: J94.2 U1.AD2(TEMP_DIODE_N)
N14124254: C304.1 J30.1 R449.2(P2)
N17330848: J30.3 R555.1(P1)
N17331023: J30.4 R557.2(P2)
N17331144: J30.5 R556.1(P1)
N17331154: J30.6 R558.2(P2)
N17331165: J30.8 R554.2(P2)
N17385130: C211.1 U21.3(V-)
N17385132: C209.1 U21.27(V+)
N17385237: TP52.1 U21.21(~{INVALID})
N17386054: C208.2 U21.24(C1-)
N17386056: C210.1 U21.1(C2+)
N17386058: C210.2 U21.2(C2-)
N17386060: C208.1 U21.28(C1+)
N17386577: R563.1(P1) R564.2(P2) U21.22(~{FOFF}) U21.23(FON)
N17400720: R566.2(P2) U21.6(RIN3) U21.7(RIN4) U21.8(RIN5)
N17400814: R567.2(P2) U21.12(DIN3)
N17485985: TP1.1 U1.D6(VDDA1P8_PMLDO)
N17737969: U1.Y18(CAM0_DATA2/MMC1_CLK) U49.1(CLKA)
N17737971: U1.AA18(CAM0_DATA3/MMC1_CMD) U49.47(CMDA)
N17737973: U1.AE19(CAM0_DATA4/MMC1_D0) U49.48(DAT0A)
N17737975: U1.AD19(CAM0_DATA5/MMC1_D1) U49.4(DAT1A)
N17737977: U1.AE20(CAM0_DATA6/MMC1_D2) U49.5(DAT2A)
N17737979: U1.AD20(CAM0_DATA7/MMC1_D3) U49.3(DAT3A)
N17738000: U1.F7(GPMC_A8/MCASP0_ACLKX) U49.45(AUD_CLKA)
N17738002: U1.G8(GPMC_A10/MCASP0_AXR0) U49.16(AUD_INA)
N17738004: U1.D8(GPMC_A11/MCASP0_AXR1) U49.17(AUD_OUTA)
N17738174: U1.B4(GPMC_A9/MCASP0_FSX) U49.46(AUD_FSYNCA)
N17738208: U1.H24(UART3_TXD) U49.13(UART_RXA)
N17738218: U1.H25(UART3_RXD) U49.15(UART_TXA)
N17738228: U1.H22(UART3_CTSn) U49.12(UART_RTSA)
N17738368: TP43.1 U1.C24(XDMA_EVENT_INTR1/CLKOUT2) U49.19(SLOWCLKA)
N17738424: R357.1(P1) U49.39(CMDB)
N17738454: R368.1(P1) U49.36(DAT0B)
N17738456: R378.1(P1) U49.37(CLKB)
N17738504: R402.2(P2) U49.6(WLAN_IRQA)
N17738506: R545.2(P2) U49.42(~{OE})
N17738510: TP39.1 U49.9(CLK_REQA)
N17738609: R375.1(P1) U49.34(DAT1B)
N17738611: R381.1(P1) U49.33(DAT2B)
N17738613: R362.1(P1) U49.35(DAT3B)
N17738615: R373.1(P1) U49.31(WLAN_IRQB)
N17738621: R366.1(P1) U49.30(WLAN_ENB)
N17738627: R363.1(P1) U49.23(UART_TXB)
N17738633: R377.1(P1) U49.25(UART_RXB)
N17738639: R369.1(P1) U49.27(UART_CTSB)
N17738645: R376.1(P1) U49.24(UART_RTSB)
N17738651: R379.1(P1) U49.41(AUD_CLKB)
N17738657: R359.1(P1) U49.40(AUD_FSYNCB)
N17738663: R364.1(P1) U49.22(AUD_INB)
N17738669: R372.1(P1) U49.21(AUD_OUTB)
N17738706: TP40.1 U49.29(CLK_REQB)
N17738715: R370.1(P1) U58.3(A)
N17738888: R360.1(P1) U59.3(A)
N17738899: R480.1(P1) U49.43(AUD_DIR)
N17753186: FB12.2 U1.E23(VDDS_CLKOUT)
N17852625: R212.2(P2) U1.R25(SPI0_CS1/MMC0_SDCD)
N18137420: TP3.1 U1.D20(VDD_MPU_MON)
N18282388: C476.1 R708.2(P2) U1.P21(VPP)
N20048058: C430.1 J31.1 R450.2(P2)
N20048095: J31.3 R550.1(P1)
N20048097: J31.4 R552.1(P1)
N20048099: J31.5 R551.1(P1)
N20048101: J31.6 R553.1(P1)
N20474796: R688.2(P2) U84.4(1A1)
N20474799: R689.2(P2) U84.5(1A2)
N20474807: R690.2(P2) U84.6(2A1)
N20474810: R691.2(P2) U84.7(2A2)
N20523631: J97.8 R694.1(P1)
N20523709: J97.9 R695.1(P1)
N20523770: J97.10 R696.1(P1)
N20523782: J97.11 R697.1(P1)
N20523824: J97.12 R698.1(P1)
N20523836: J97.13 R699.1(P1)
N20523974: J97.14 R700.1(P1)
N20524011: J97.15 R701.1(P1)
N20524218: J97.17 R702.1(P1)
N20541736: J99.1 R707.2(P2)
N20704230: J94.1 U1.AD1(TEMP_DIODE_P)
N20725331: C295.1 R714.1(P1) Y7.1
N20991049: J42.4 R709.1(P1)
N21038713: R704.1(P1) U86.4(Y)
N21039007: J97.32 R622.1(P1)
N21039080: J97.29 R703.2(P2)

Not connected (* = marked no-connect by the designer): J10 10(#10_MMC+/MMCM) 11(#11_MMC+/MMCM) 12(#12_MMC+/MMCM) 13(#13_MMC+/MMCM) 25(#10_miniSD) 26(#11_miniSD); J19 1* 4* 6* 9*; J21 10* 12* 14* 16* 17* 21* 23* 25* 27* 29* 31* 33* 36* 38* 40* 41* 43* 44* 45* 46* 49* 51* 53* 55* 57* 59* 61* 65* 67* 69* 71* 73* 74* 75* 78* 79* 80* 81* 82* 84* 85* 86* 88* 90* 91* 93* 94* 96* 98* 99* 100*; J31 8*; J34 17* 18*; J39 5*; J90 18* 20* 22* 24*; J97 4* 5* 6* 18* 19* 20* 21* 22* 23* 24* 26* 28* 30* 31* 33* 35* 37* 39*; SCKT1 MCH1* MCH2* MCH3* MCH4*; U1 H21(TESTOUT)*; U7 4(NC4)* 5(NC5)* 6(NC6)* 11(NC11)* 12(NC12)* 13(NC13)* 14(NC14)*; U10 4(NC1)* 9(NC2)*; U11 2(NC)*; U21 11(DOUT3)* 15(ROUT5)* 16(ROUT4)* 17(ROUT3)* 20(ROUT2B)*; U22 18(ROUT2)*; U86 1(NC)*; Y7 2* 3*

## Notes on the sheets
sheet 17
- UART #1 RS-232
sheet 18
- POWER MONITORS
- VDD CORE
- VDD MPU
- ADDRESS:1000001 (41H)
- ADDRESS:1000000 (40H)
- VAM438X_DDR
- V1_8D
- ADDRESS:1000010 (42H)
- ADDRESS:1000011 (43H)
- V3_3D
- LPDDR2
- ADDRESS:1000100 (44H)
- ADDRESS:1000101 (45H)
- Note :- Put the Shut to J101 & J102  to connect the power monitor I2C lines to the processor I2C0 bus
sheet 20
- UART #0 RS-232
sheet 22
- External Clock IN
sheet 24
- 40-PIN AUTOMATION HEADER
- BOOT SWITCHES SHOULD BE SET
  TO OFF FOR PULLDOWNS.
  AUTOMATION WILL DRIVE HIGH TO OVERRIDE.
sheet 25
- SD/MMC0 Connector
sheet 26
- QSPI Interface
